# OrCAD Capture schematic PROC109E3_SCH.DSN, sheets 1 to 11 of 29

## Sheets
1 02. REVISION HISTORY: title: REVISION HISTORY; rev: E3
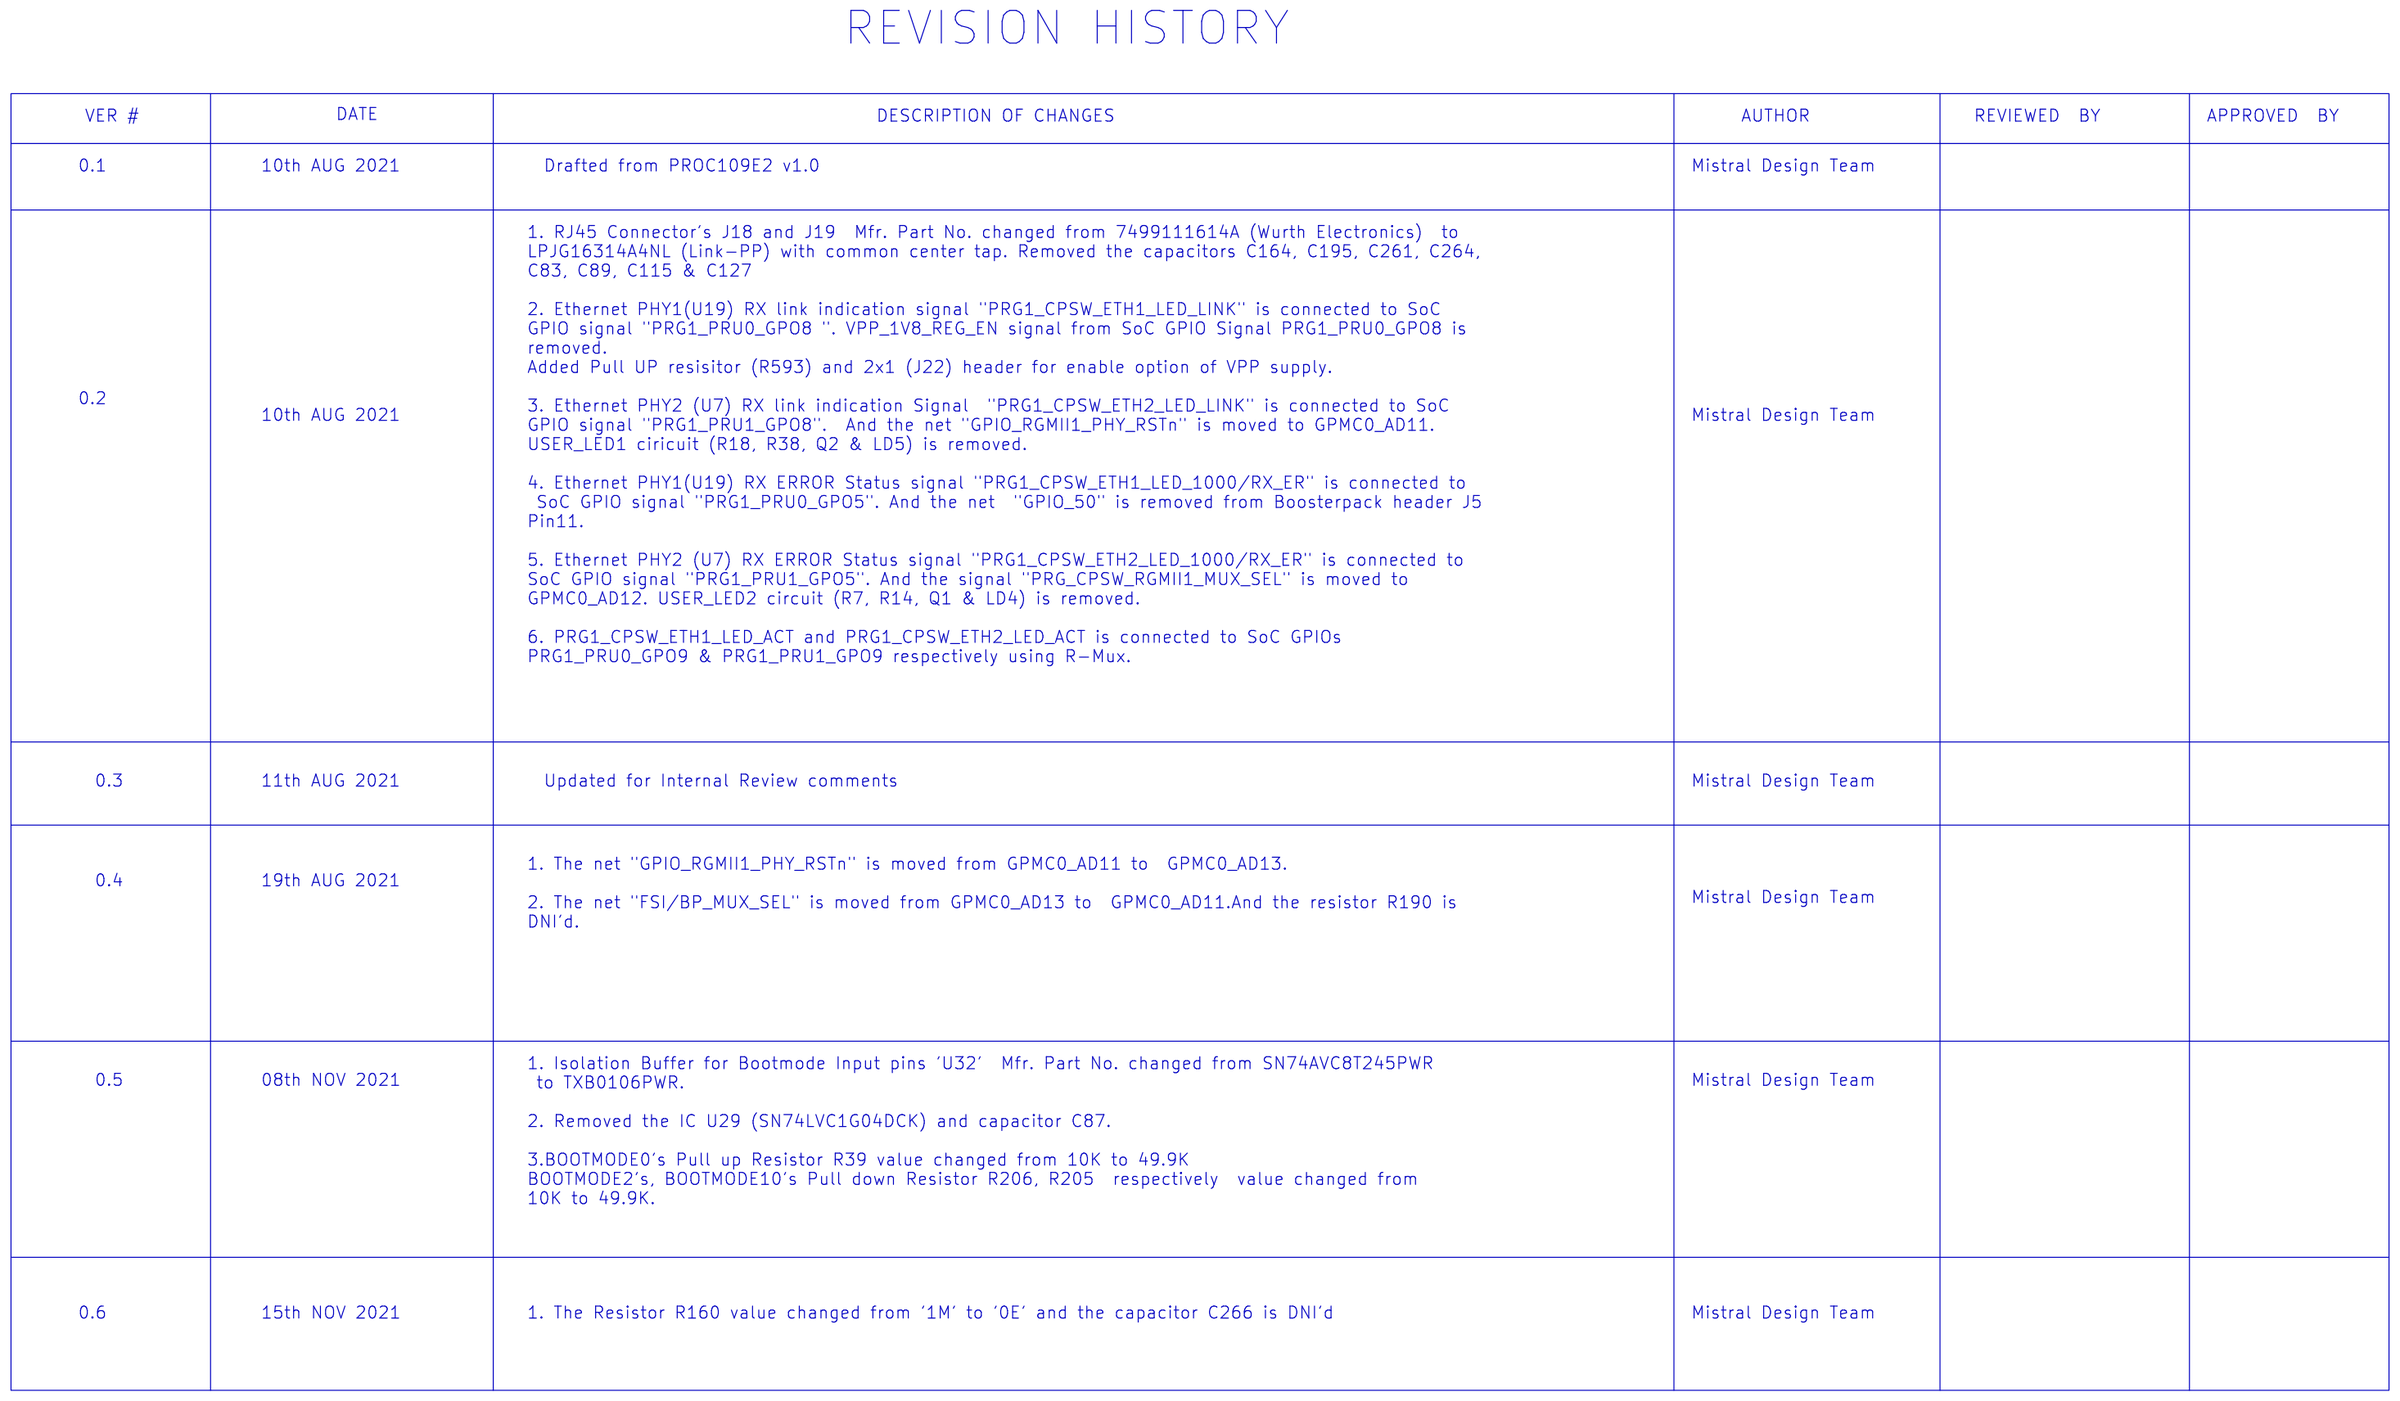
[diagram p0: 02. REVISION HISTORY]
2 01. TABLE OF CONTENTS: title: TABLE OF CONTENTS
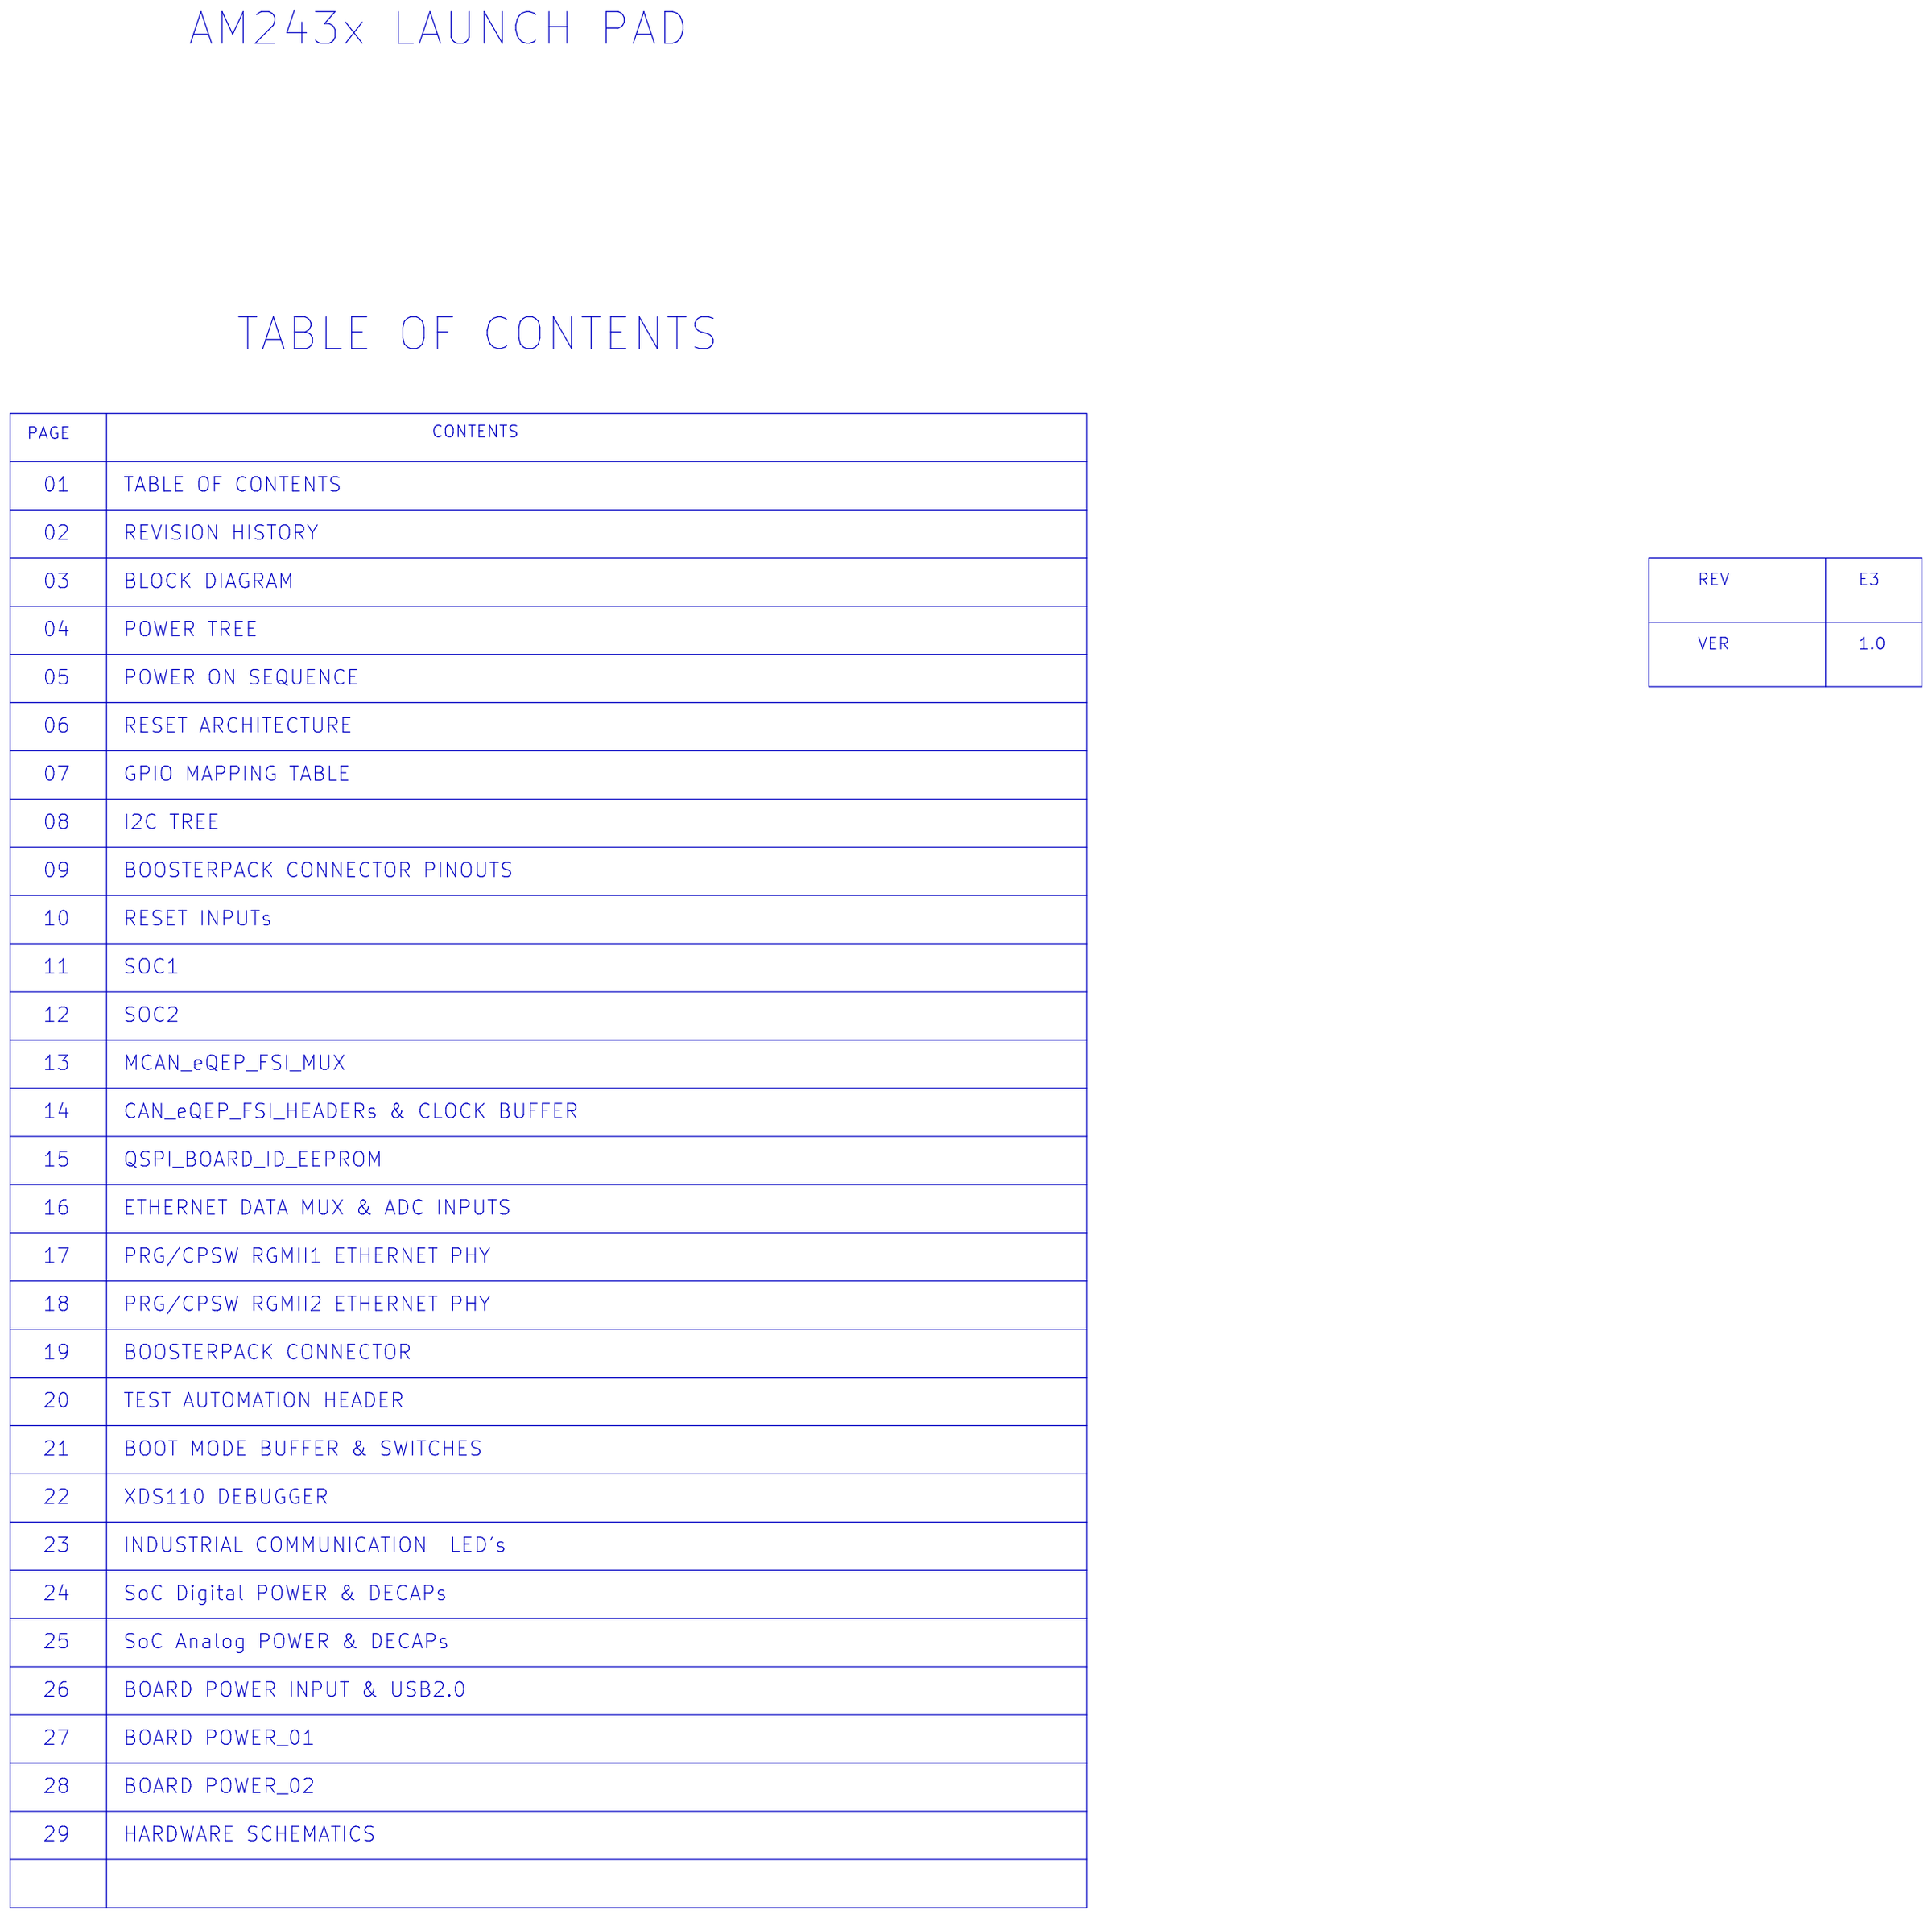
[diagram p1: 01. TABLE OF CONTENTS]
3 03. BLOCK DIAGRAM: title: BLOCK DIAGRAM
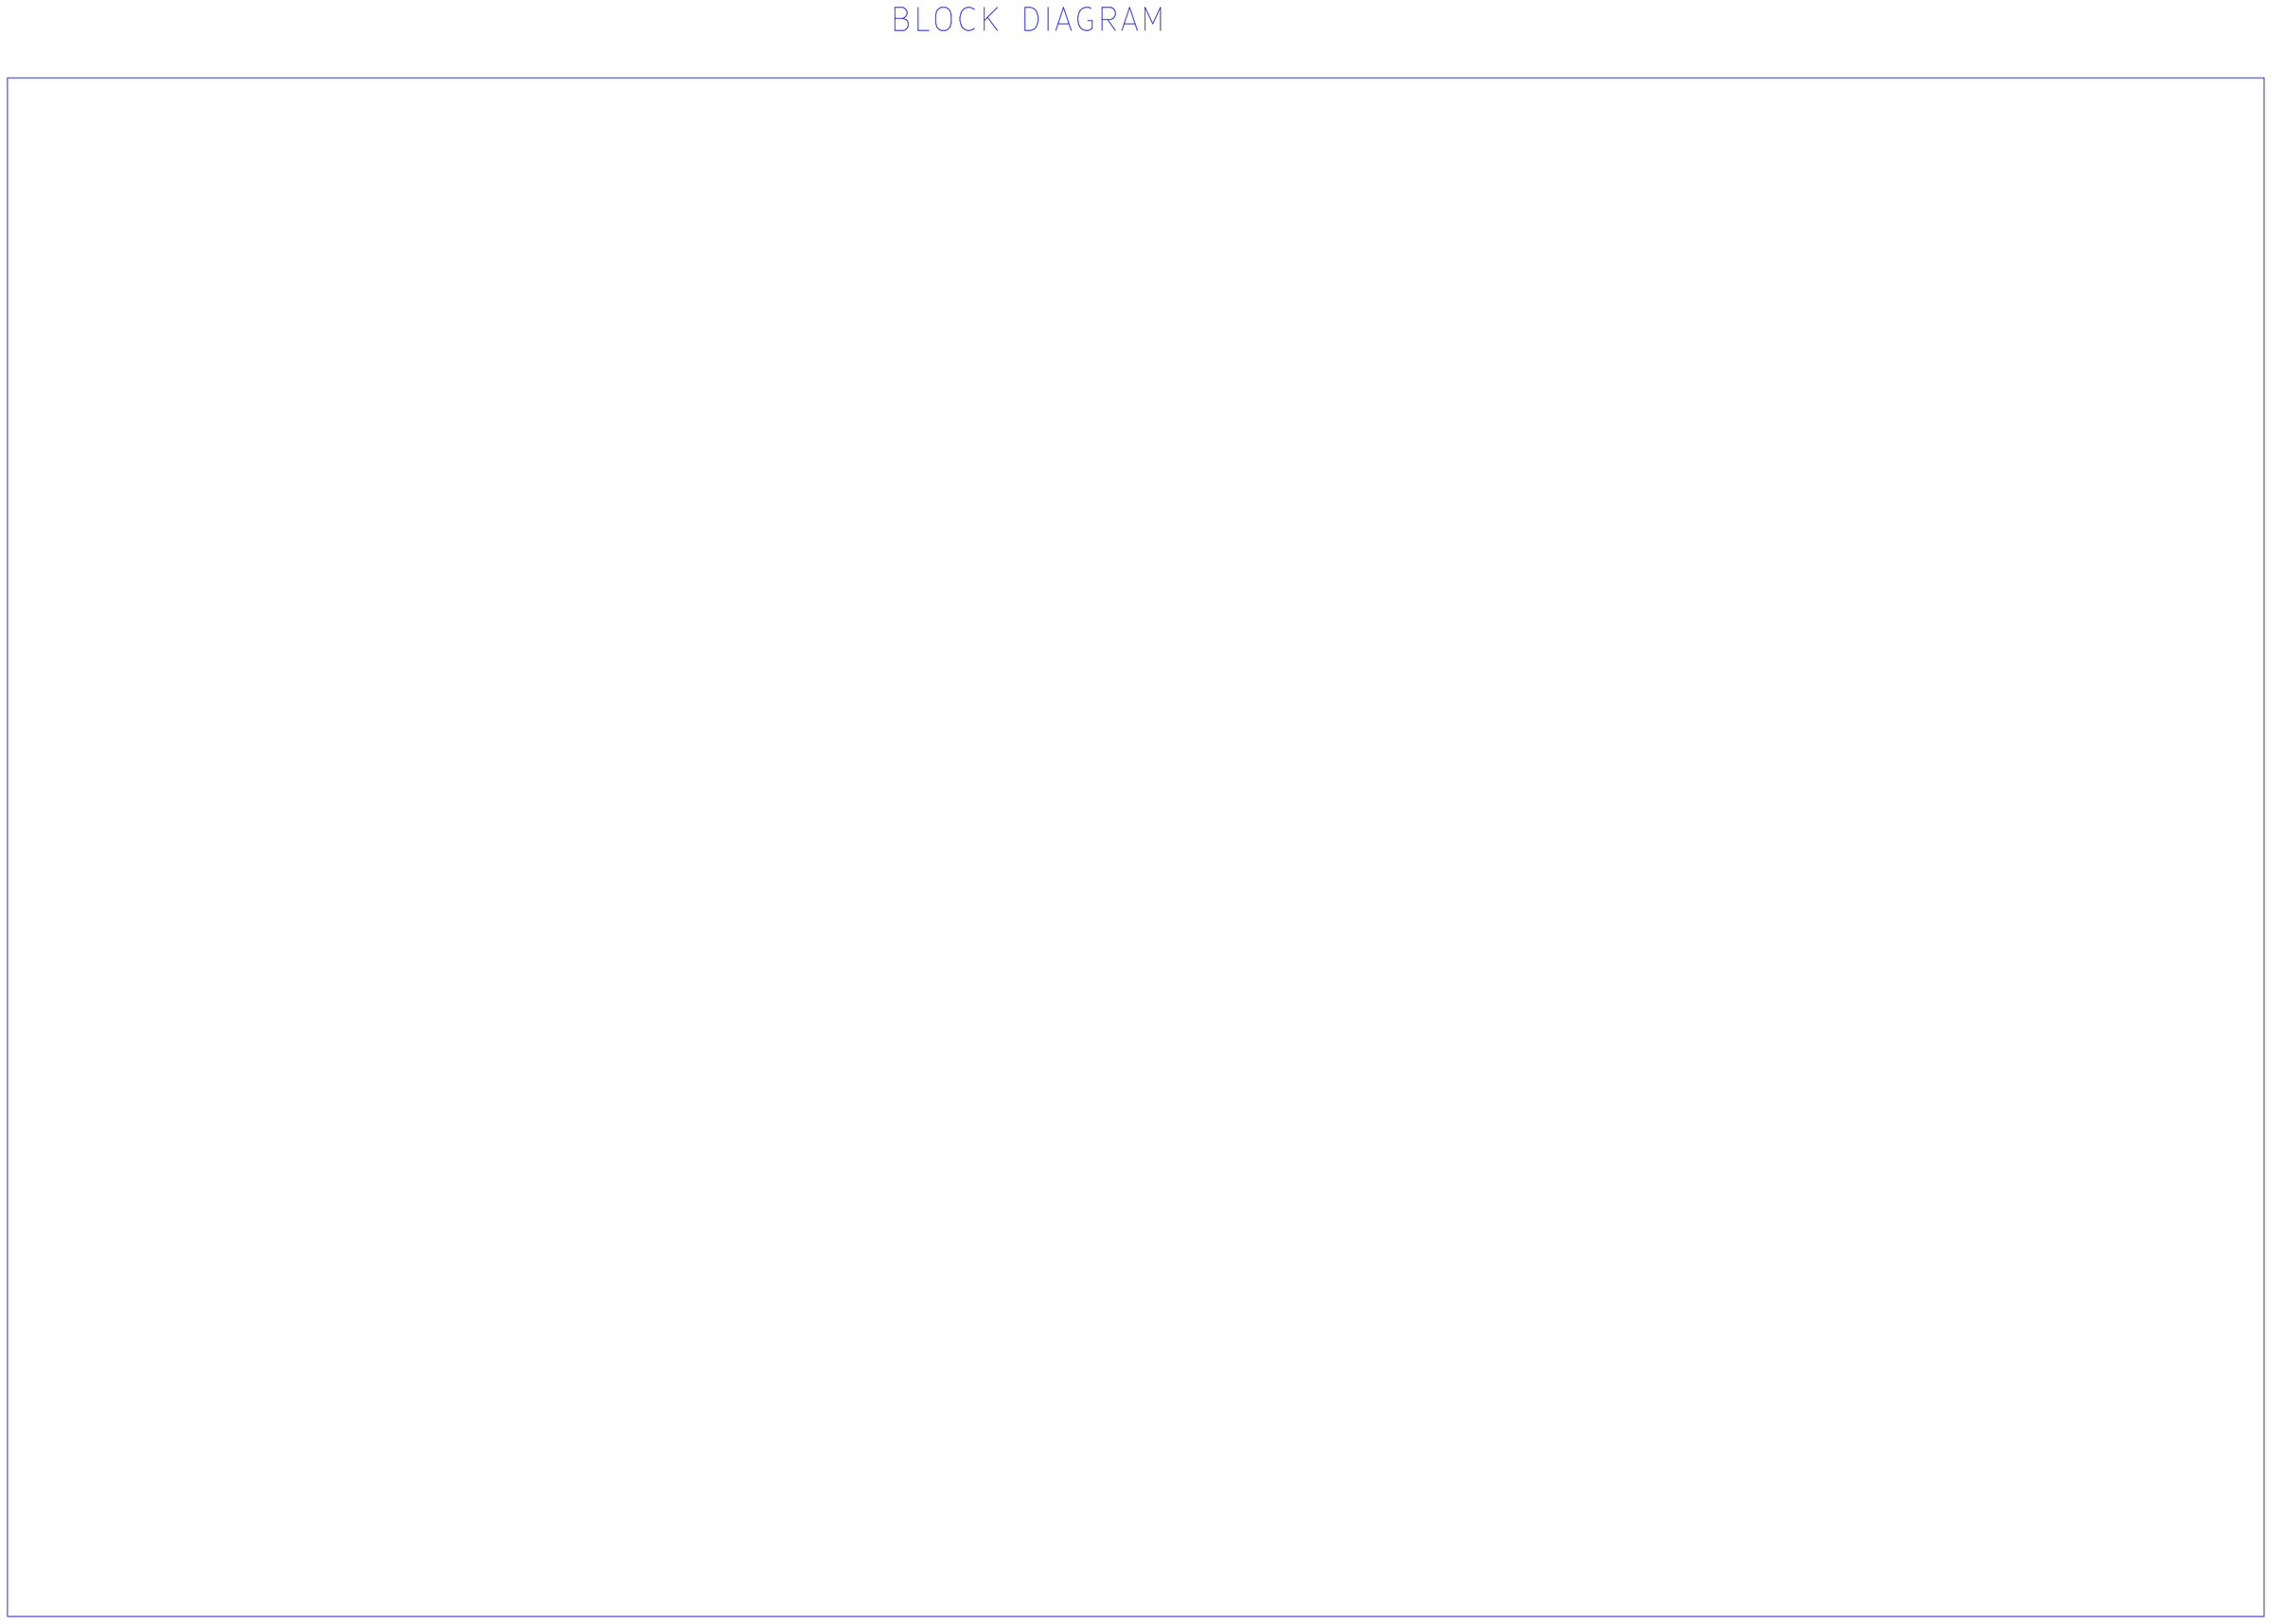
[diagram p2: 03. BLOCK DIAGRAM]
4 04. POWER TREE: title: POWER TREE
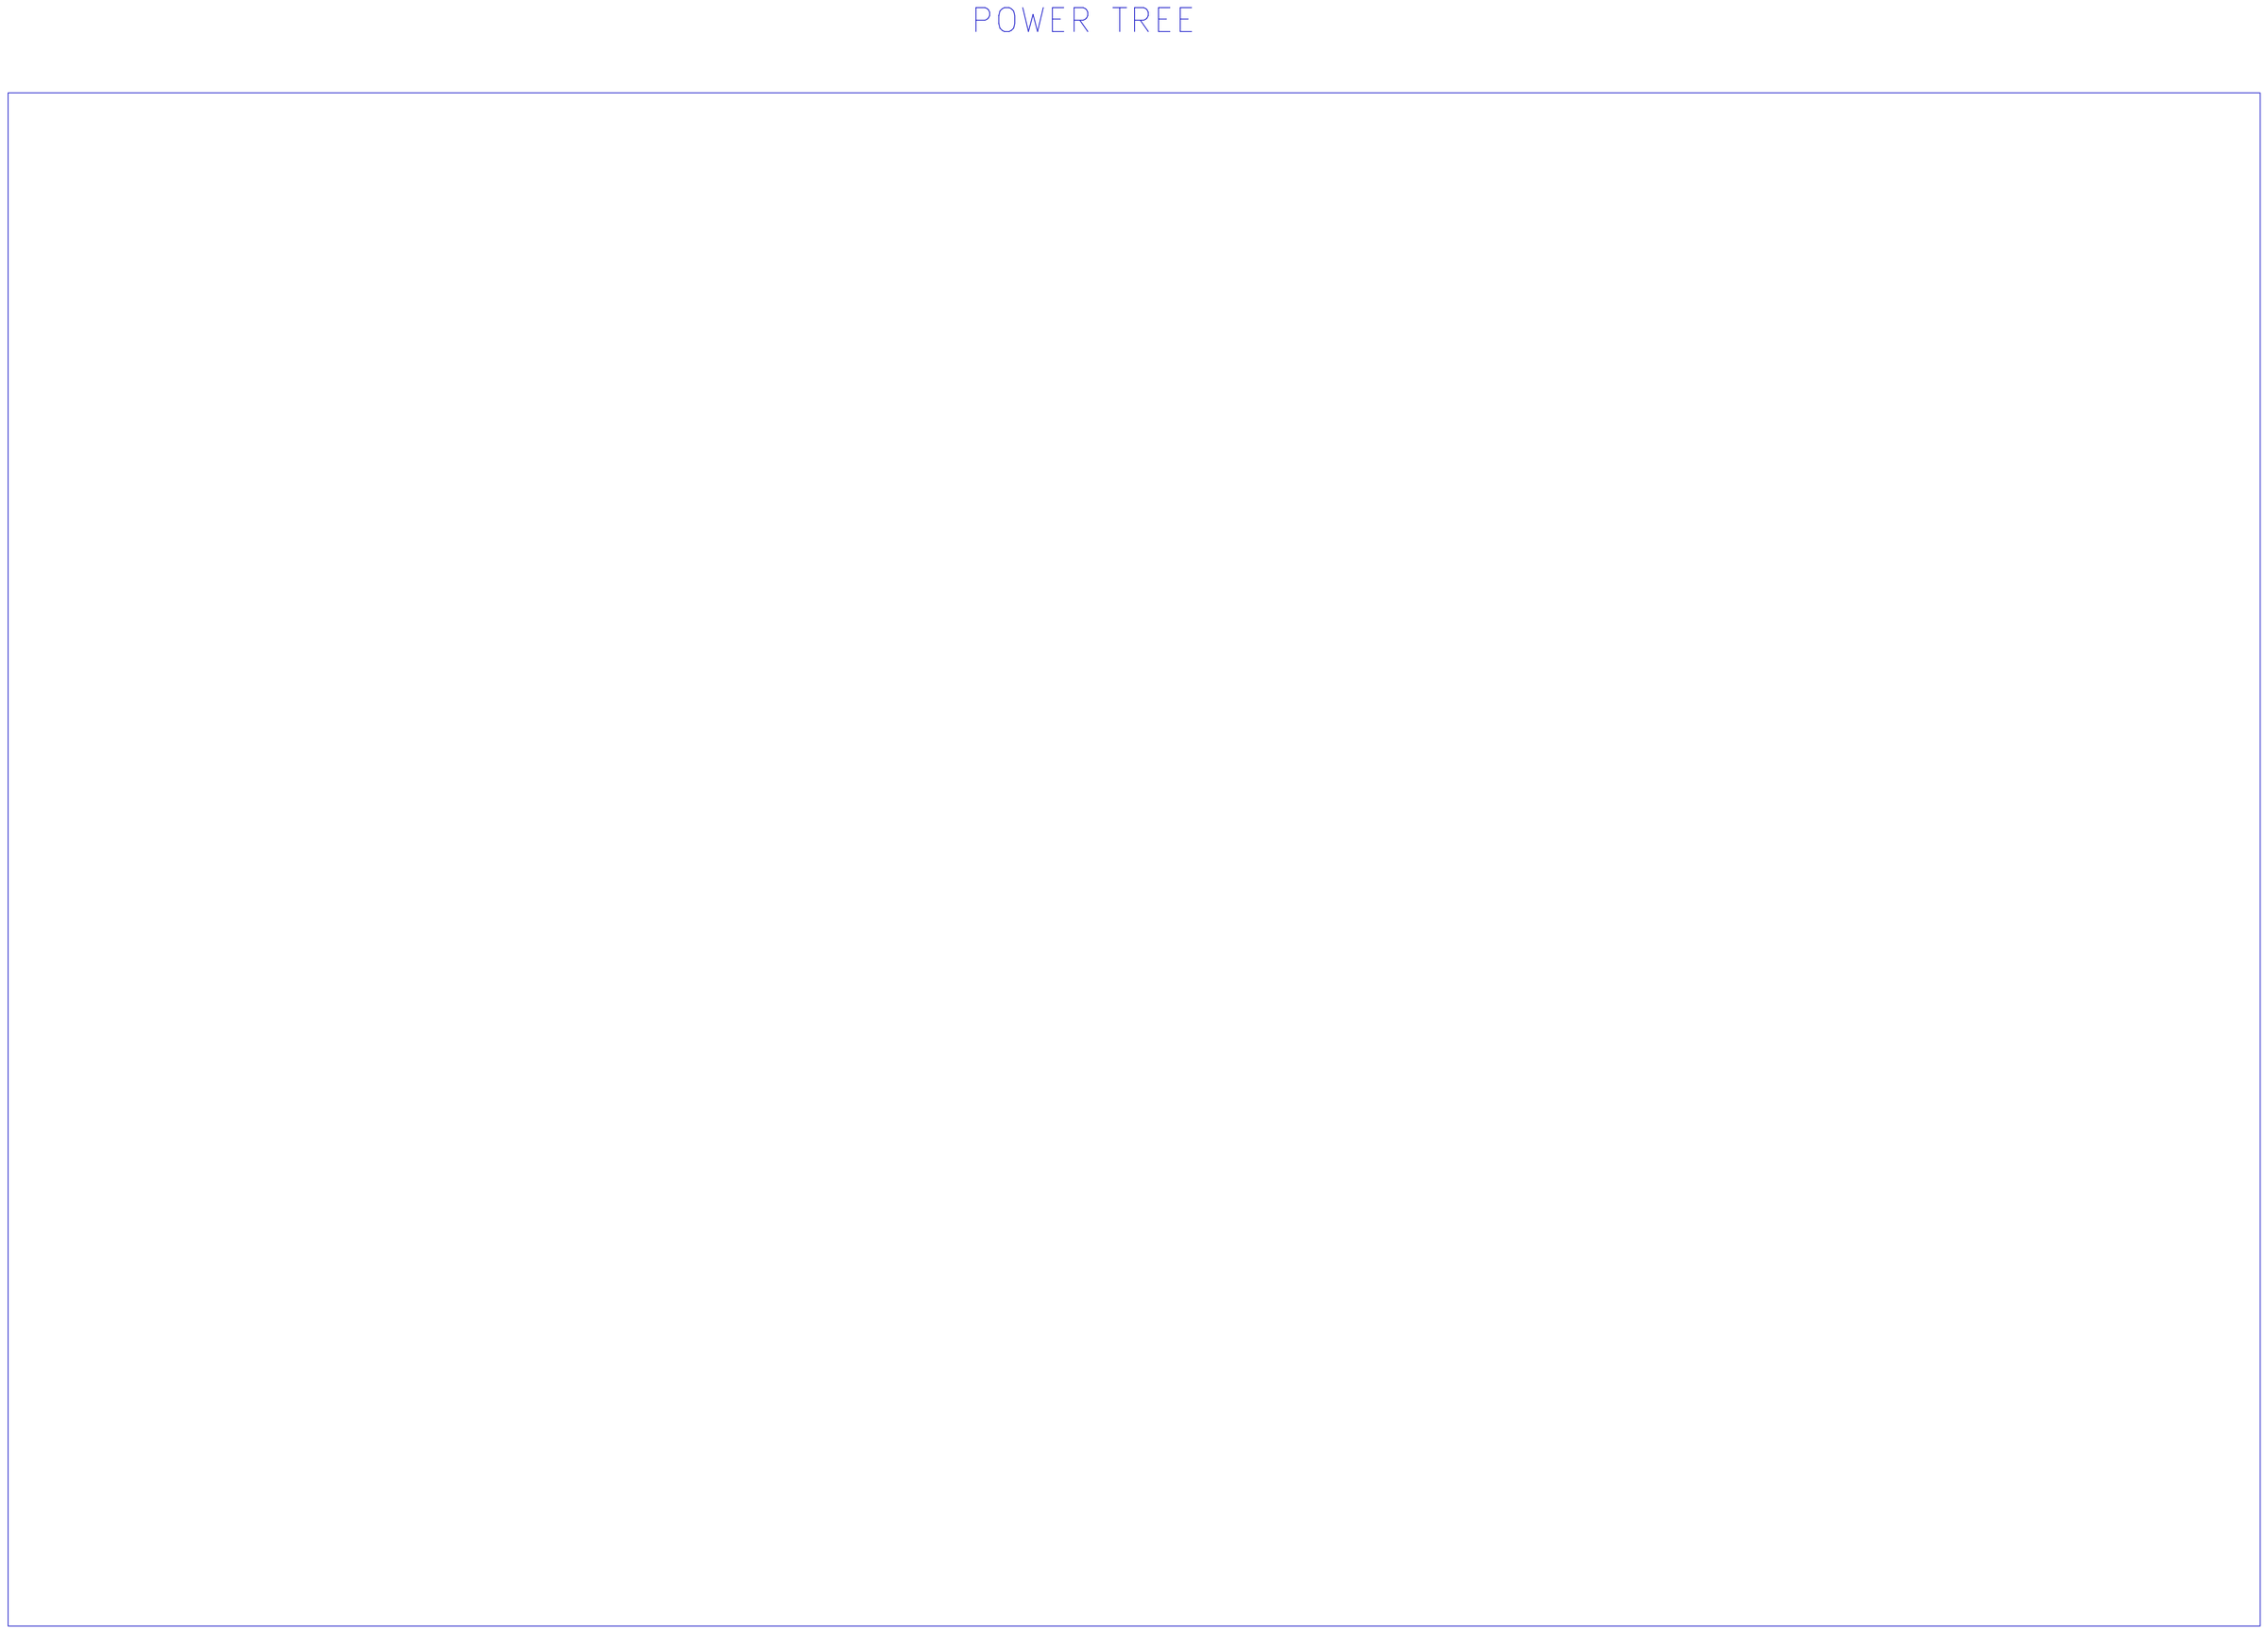
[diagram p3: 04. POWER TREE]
5 05. POWER ON SEQUENCE: title: POWER ON SEQUENCE
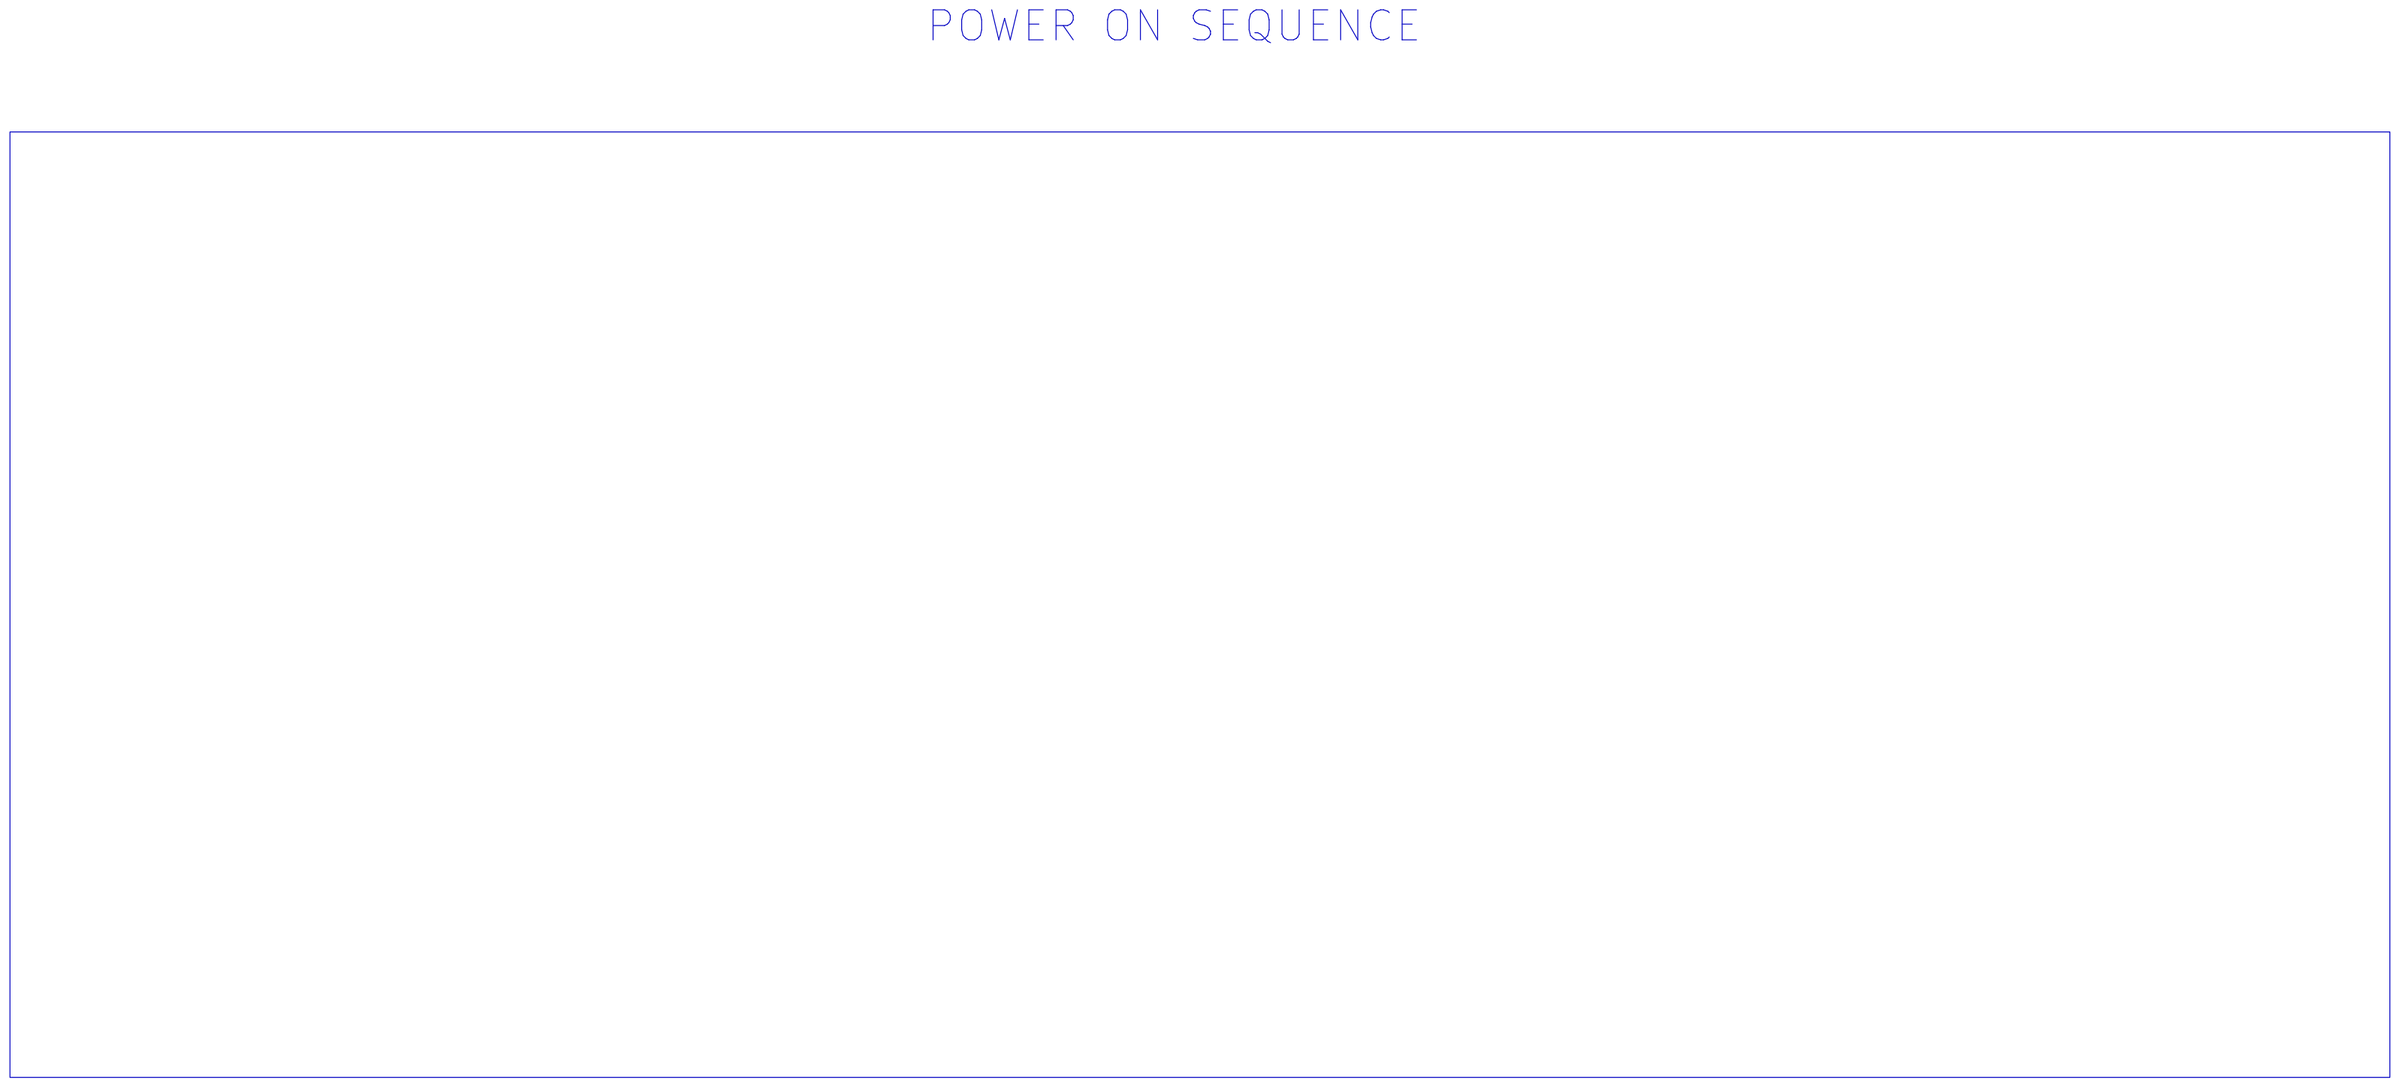
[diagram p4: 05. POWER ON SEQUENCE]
6 06. RESET ARCHITECTURE: title: RESET ARCHITECTURE
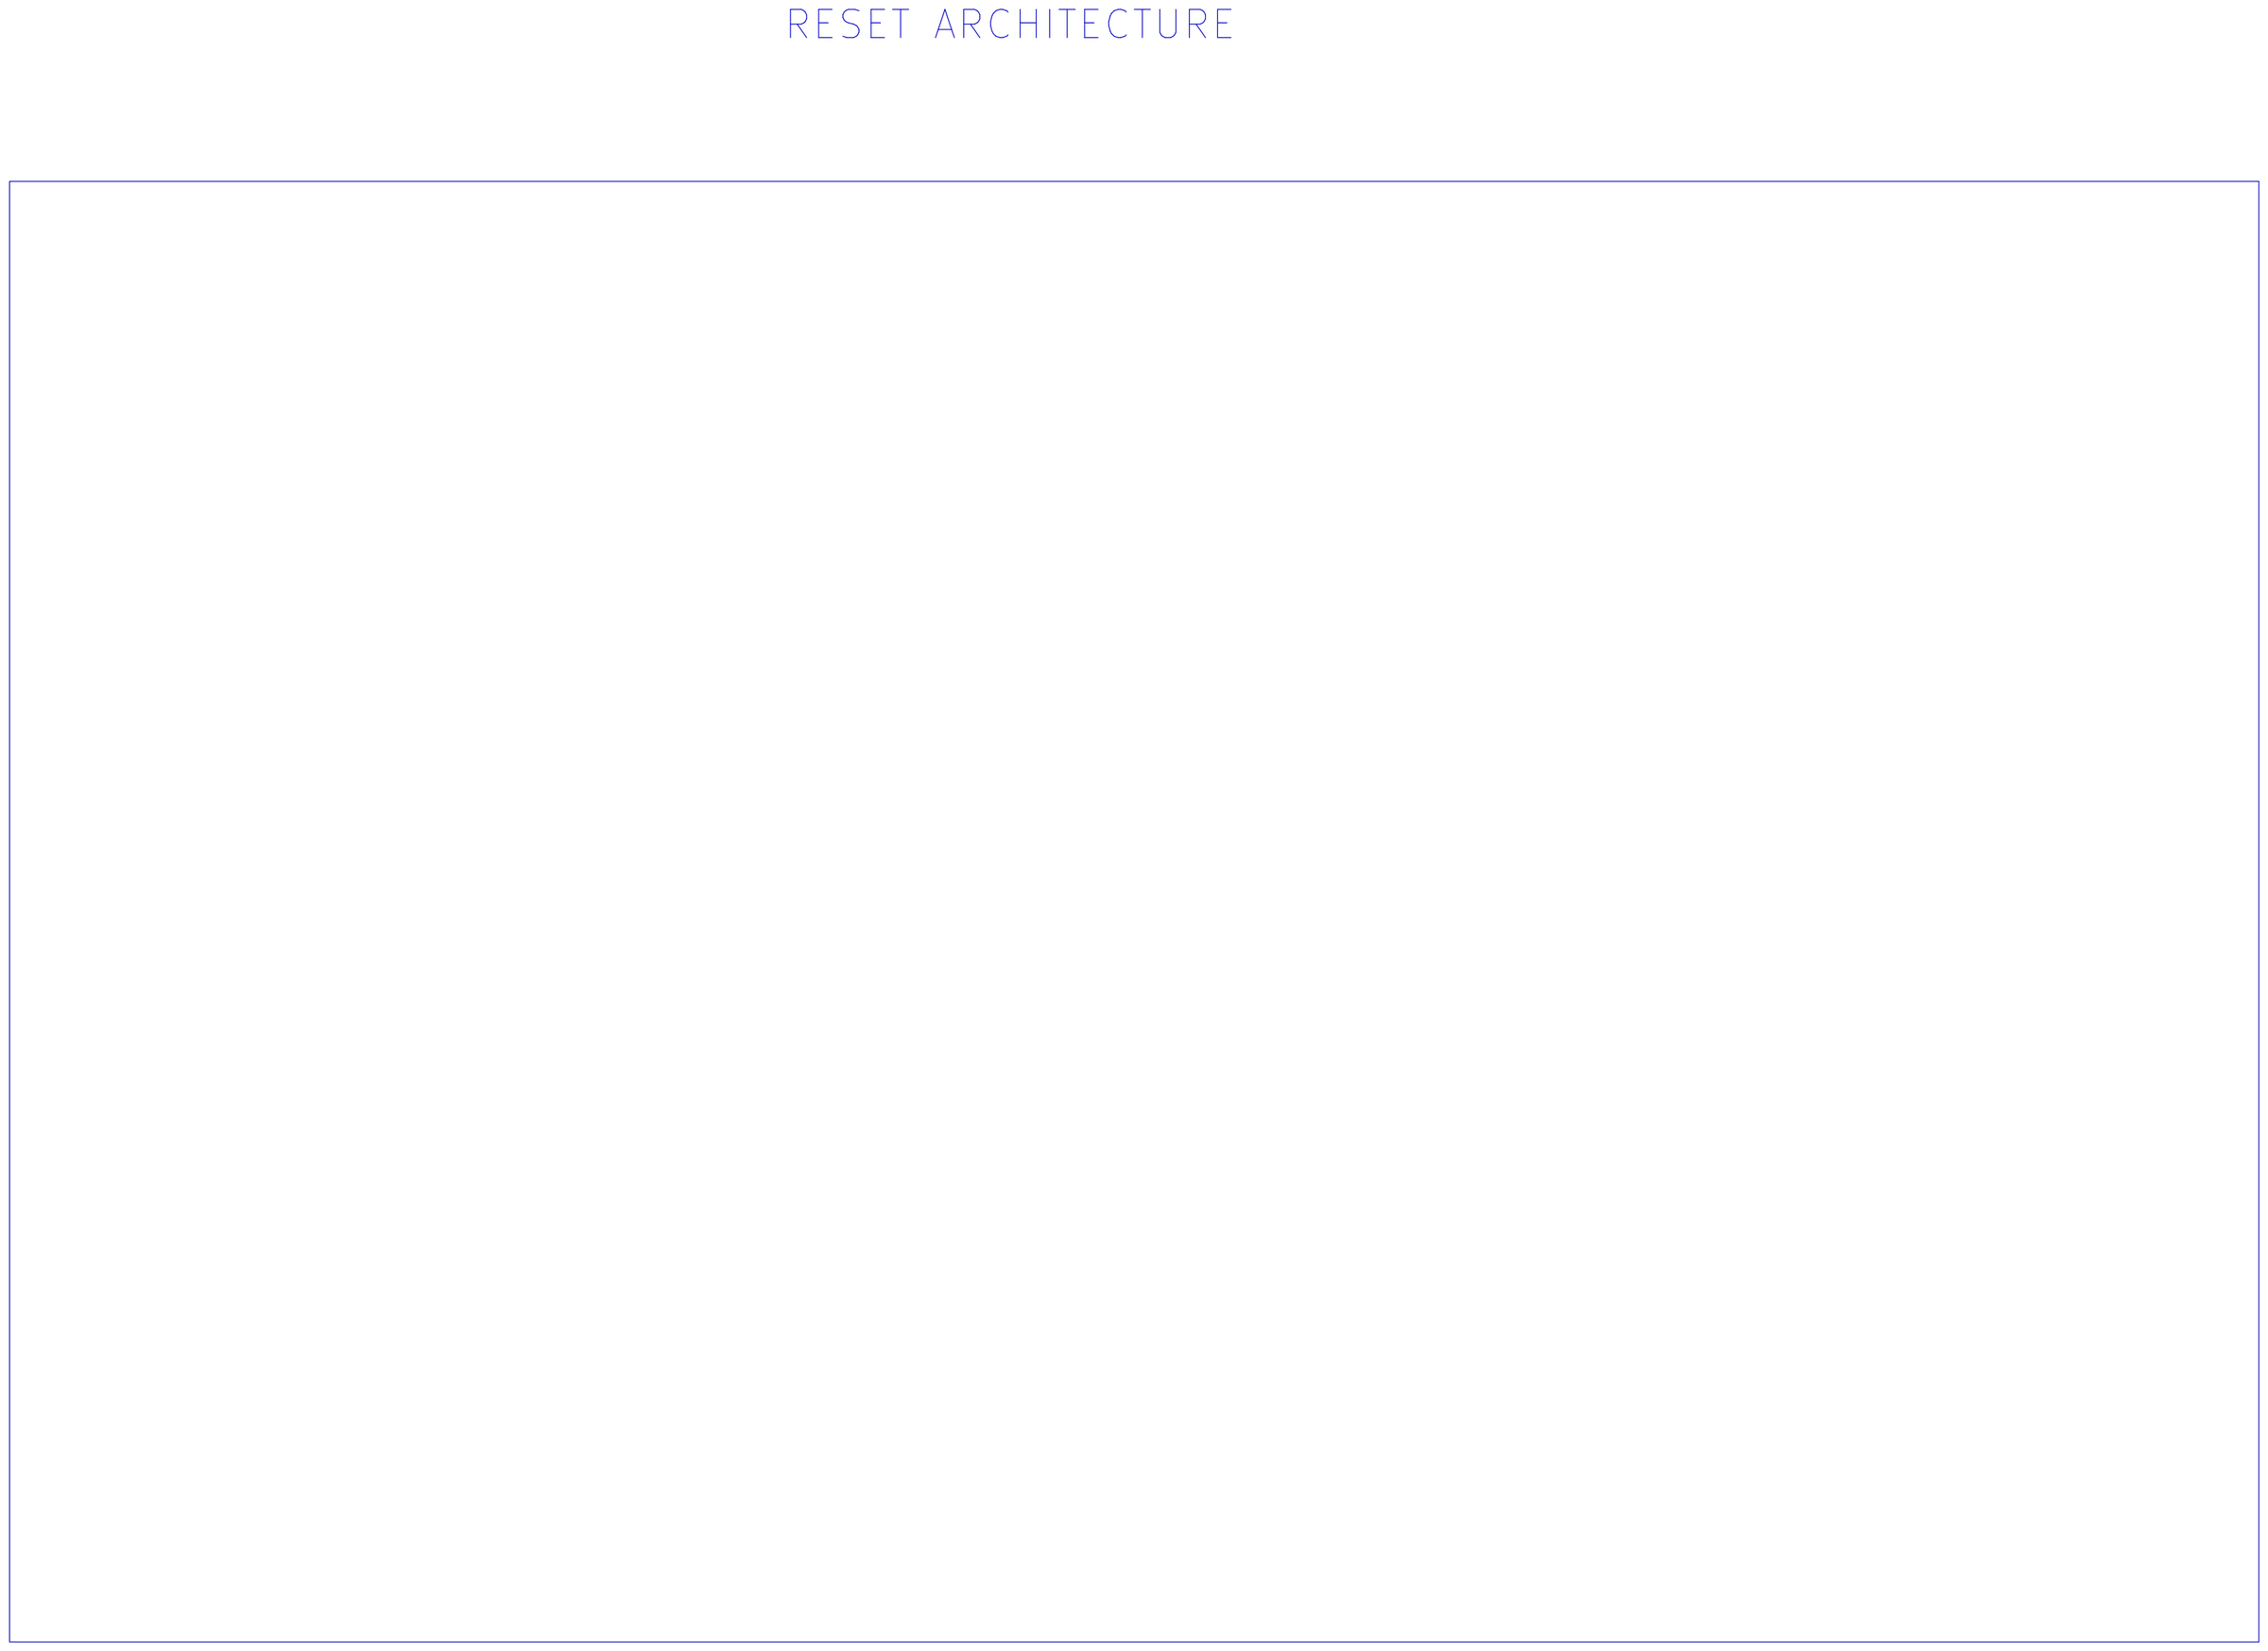
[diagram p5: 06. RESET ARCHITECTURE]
7 07. GPIO MAPPING TABLE: title: GPIO MAPPING TABLE
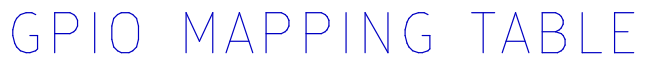
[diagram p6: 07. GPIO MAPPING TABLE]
8 08. I2C TREE: title: I2C TREE
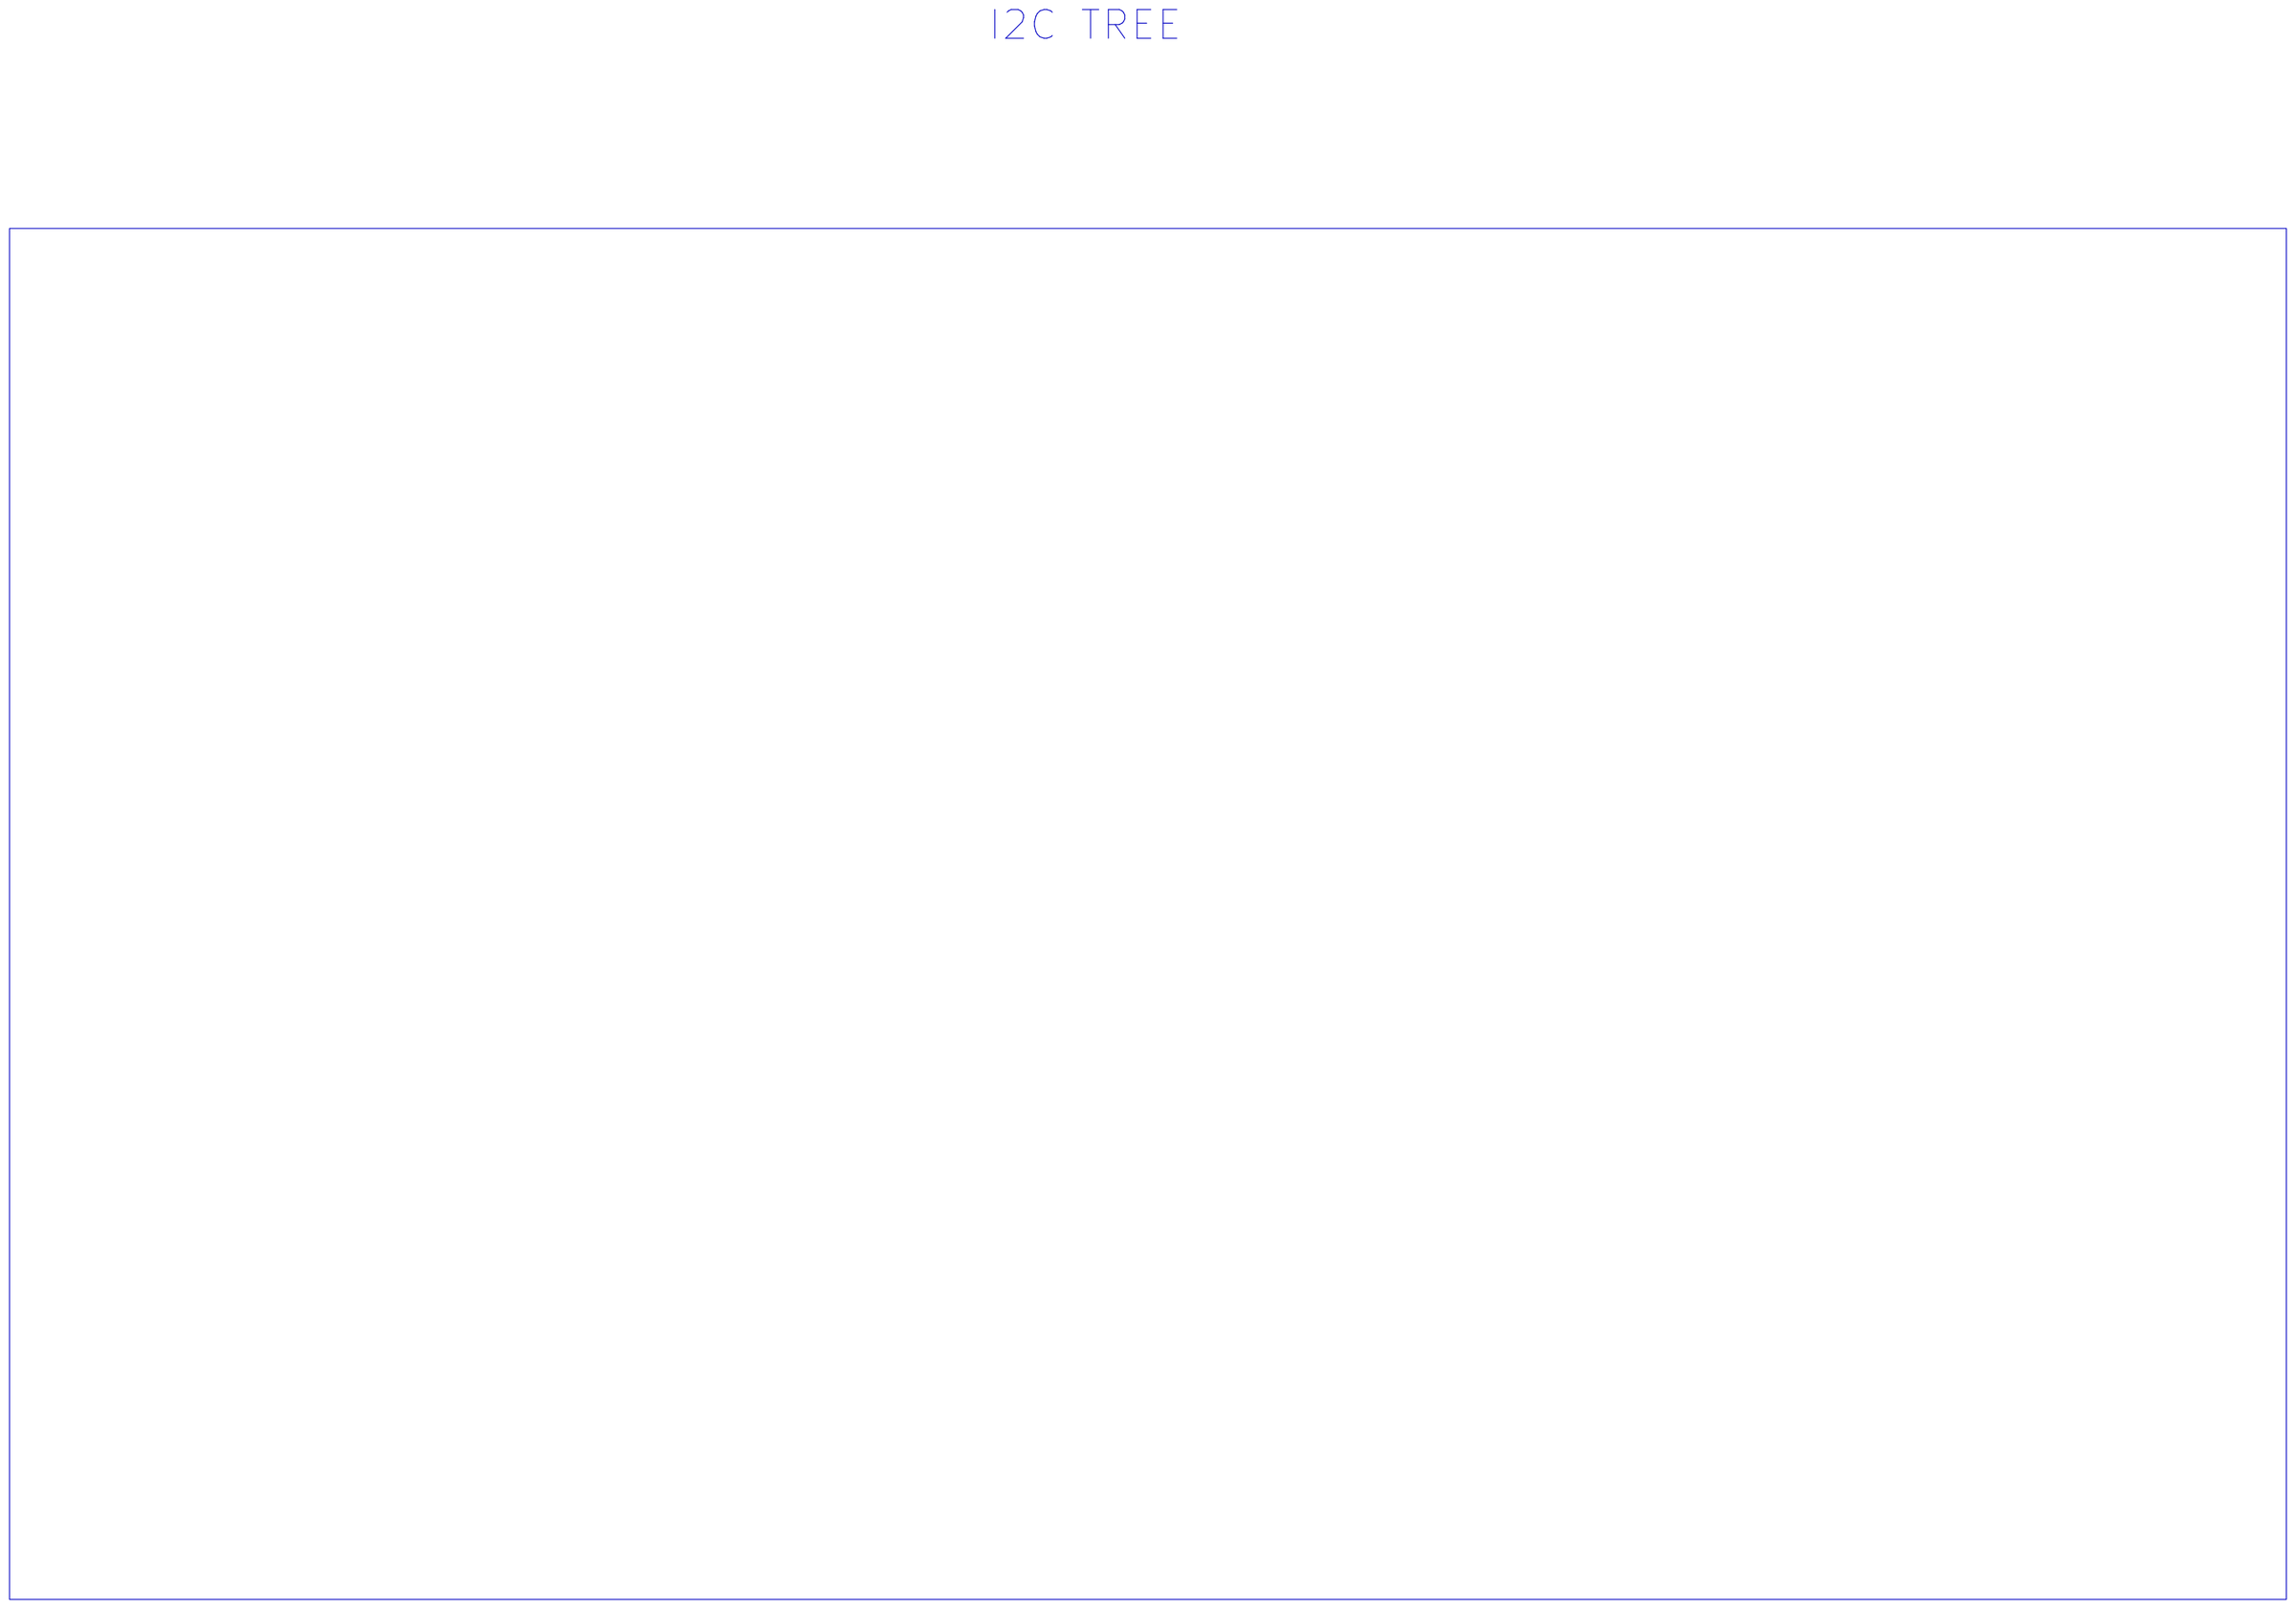
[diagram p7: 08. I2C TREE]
9 09. BOOSTERPACK CONN PINOUTs: title: BOOSTERPACK CONNECTOR PINOUTS
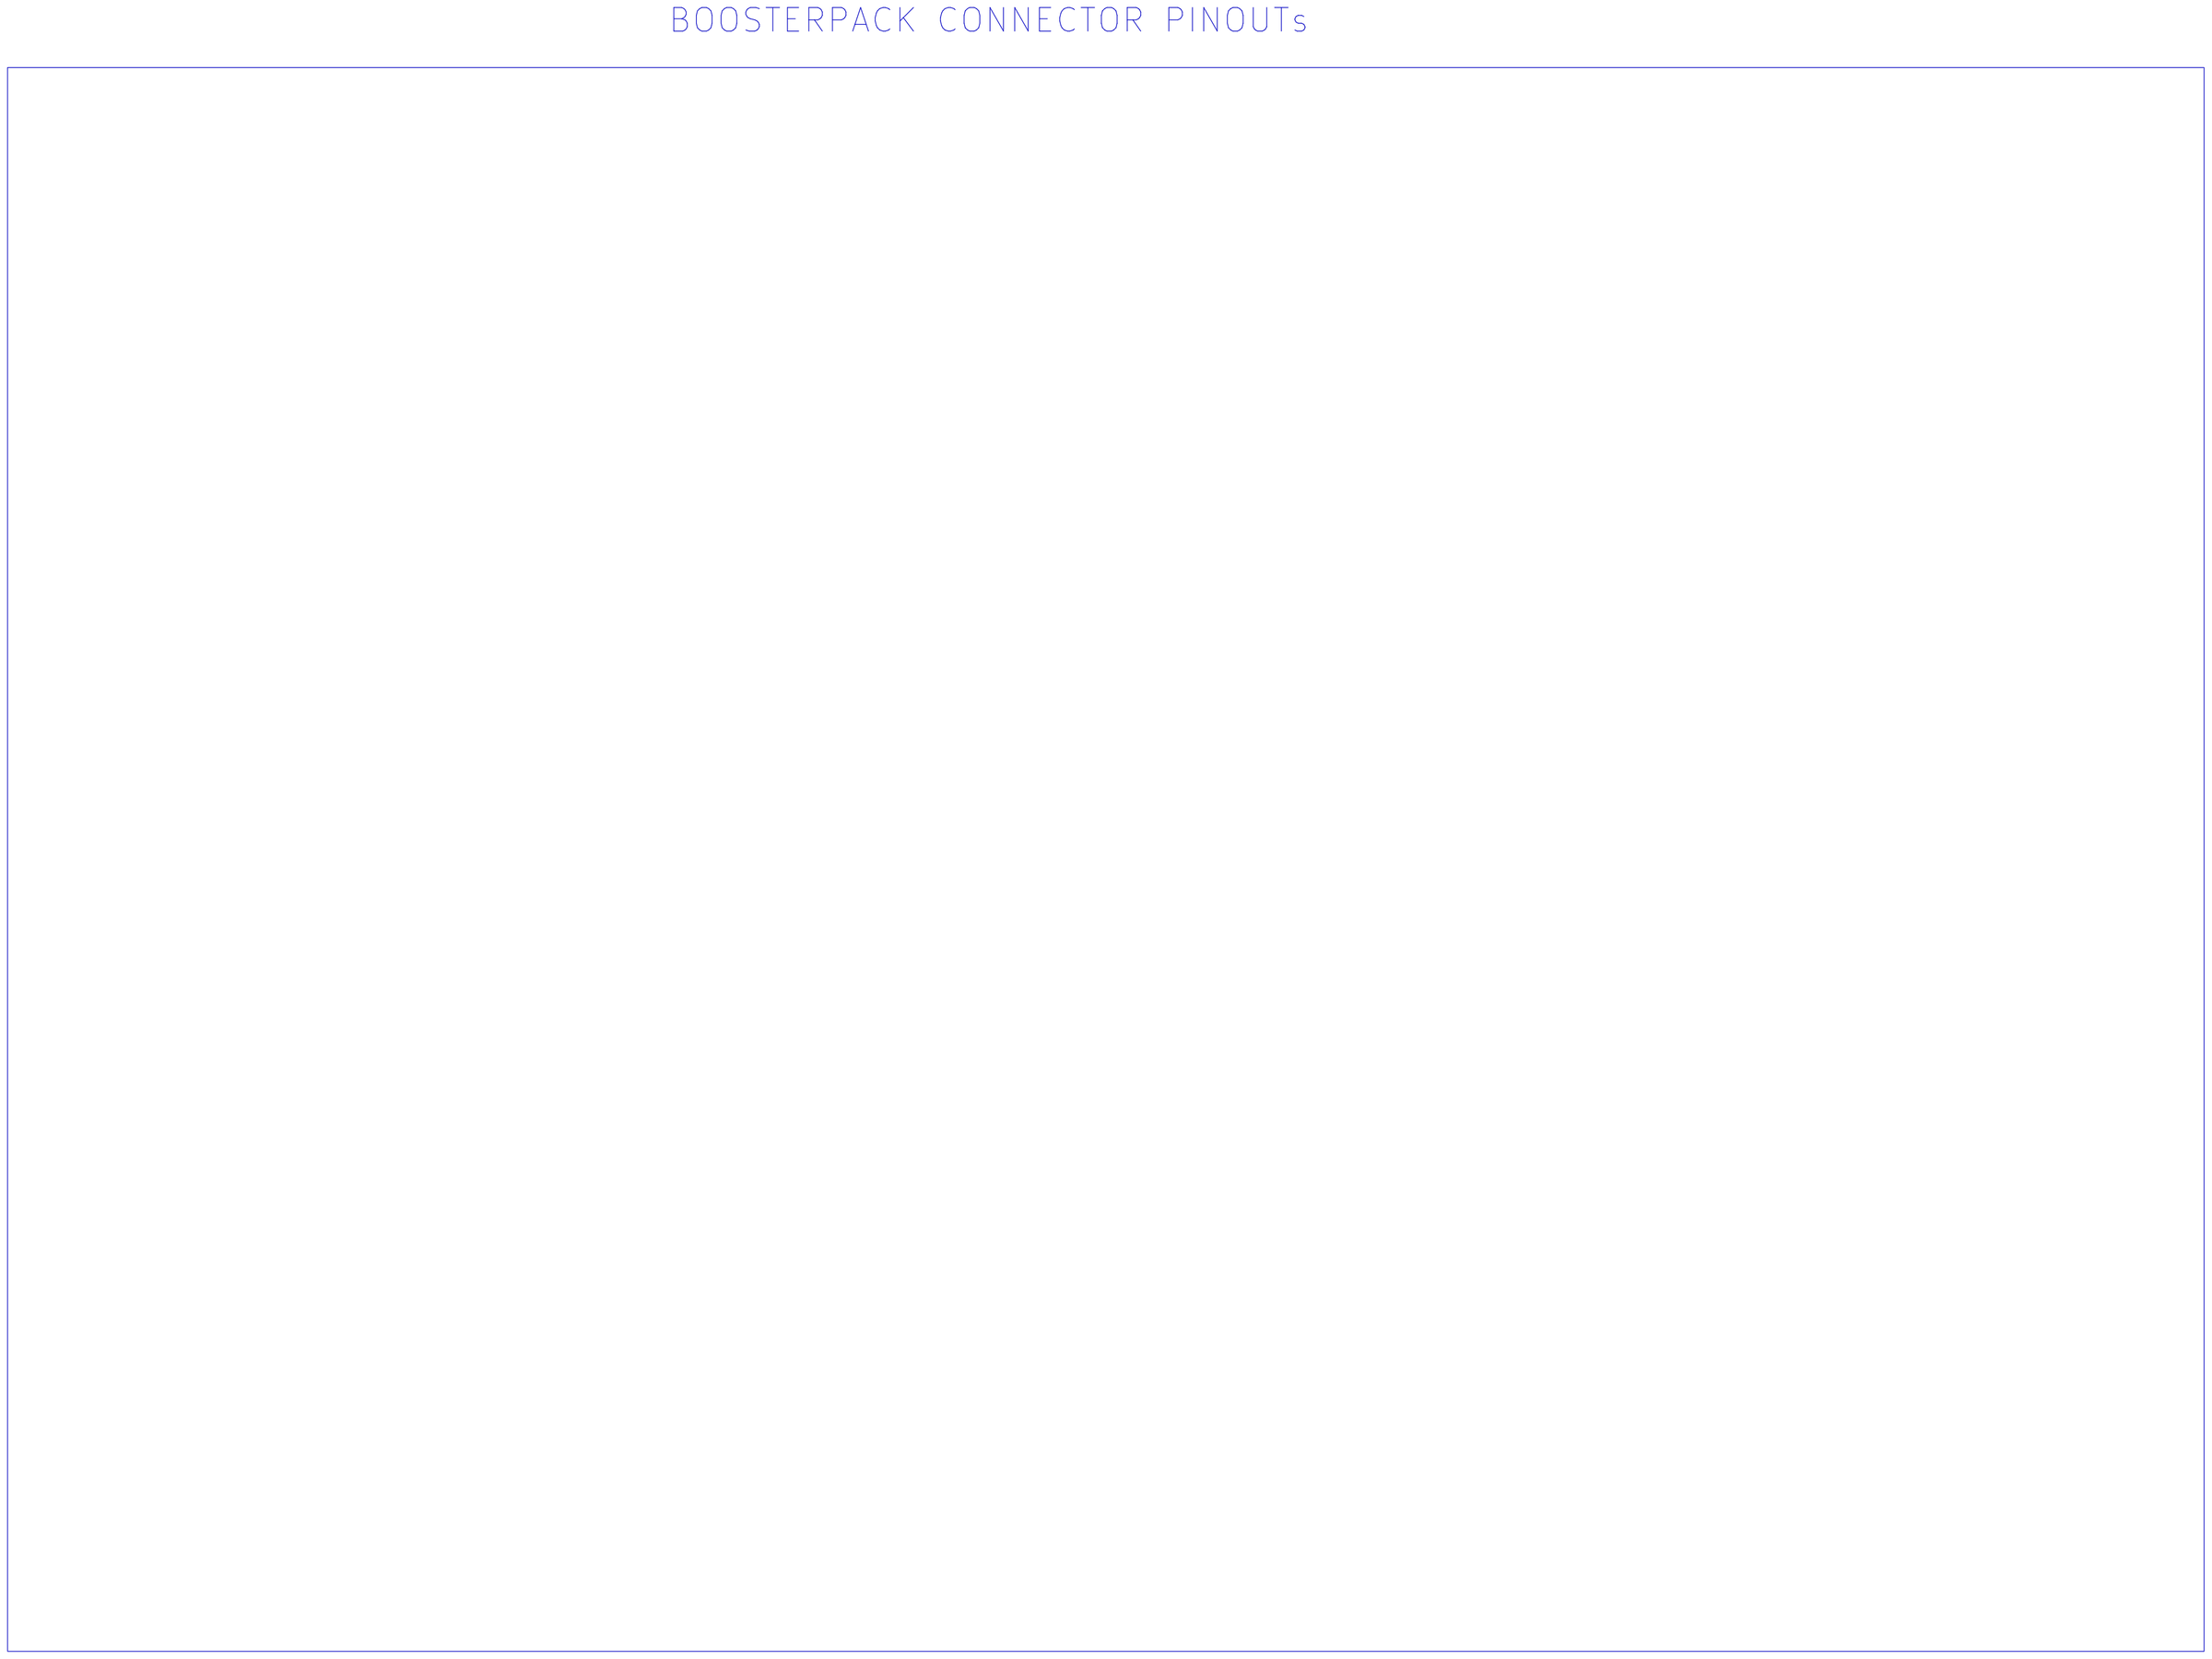
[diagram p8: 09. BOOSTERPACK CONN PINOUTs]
10 10. RESET_INPUTs: size C; title: RESET INPUTs
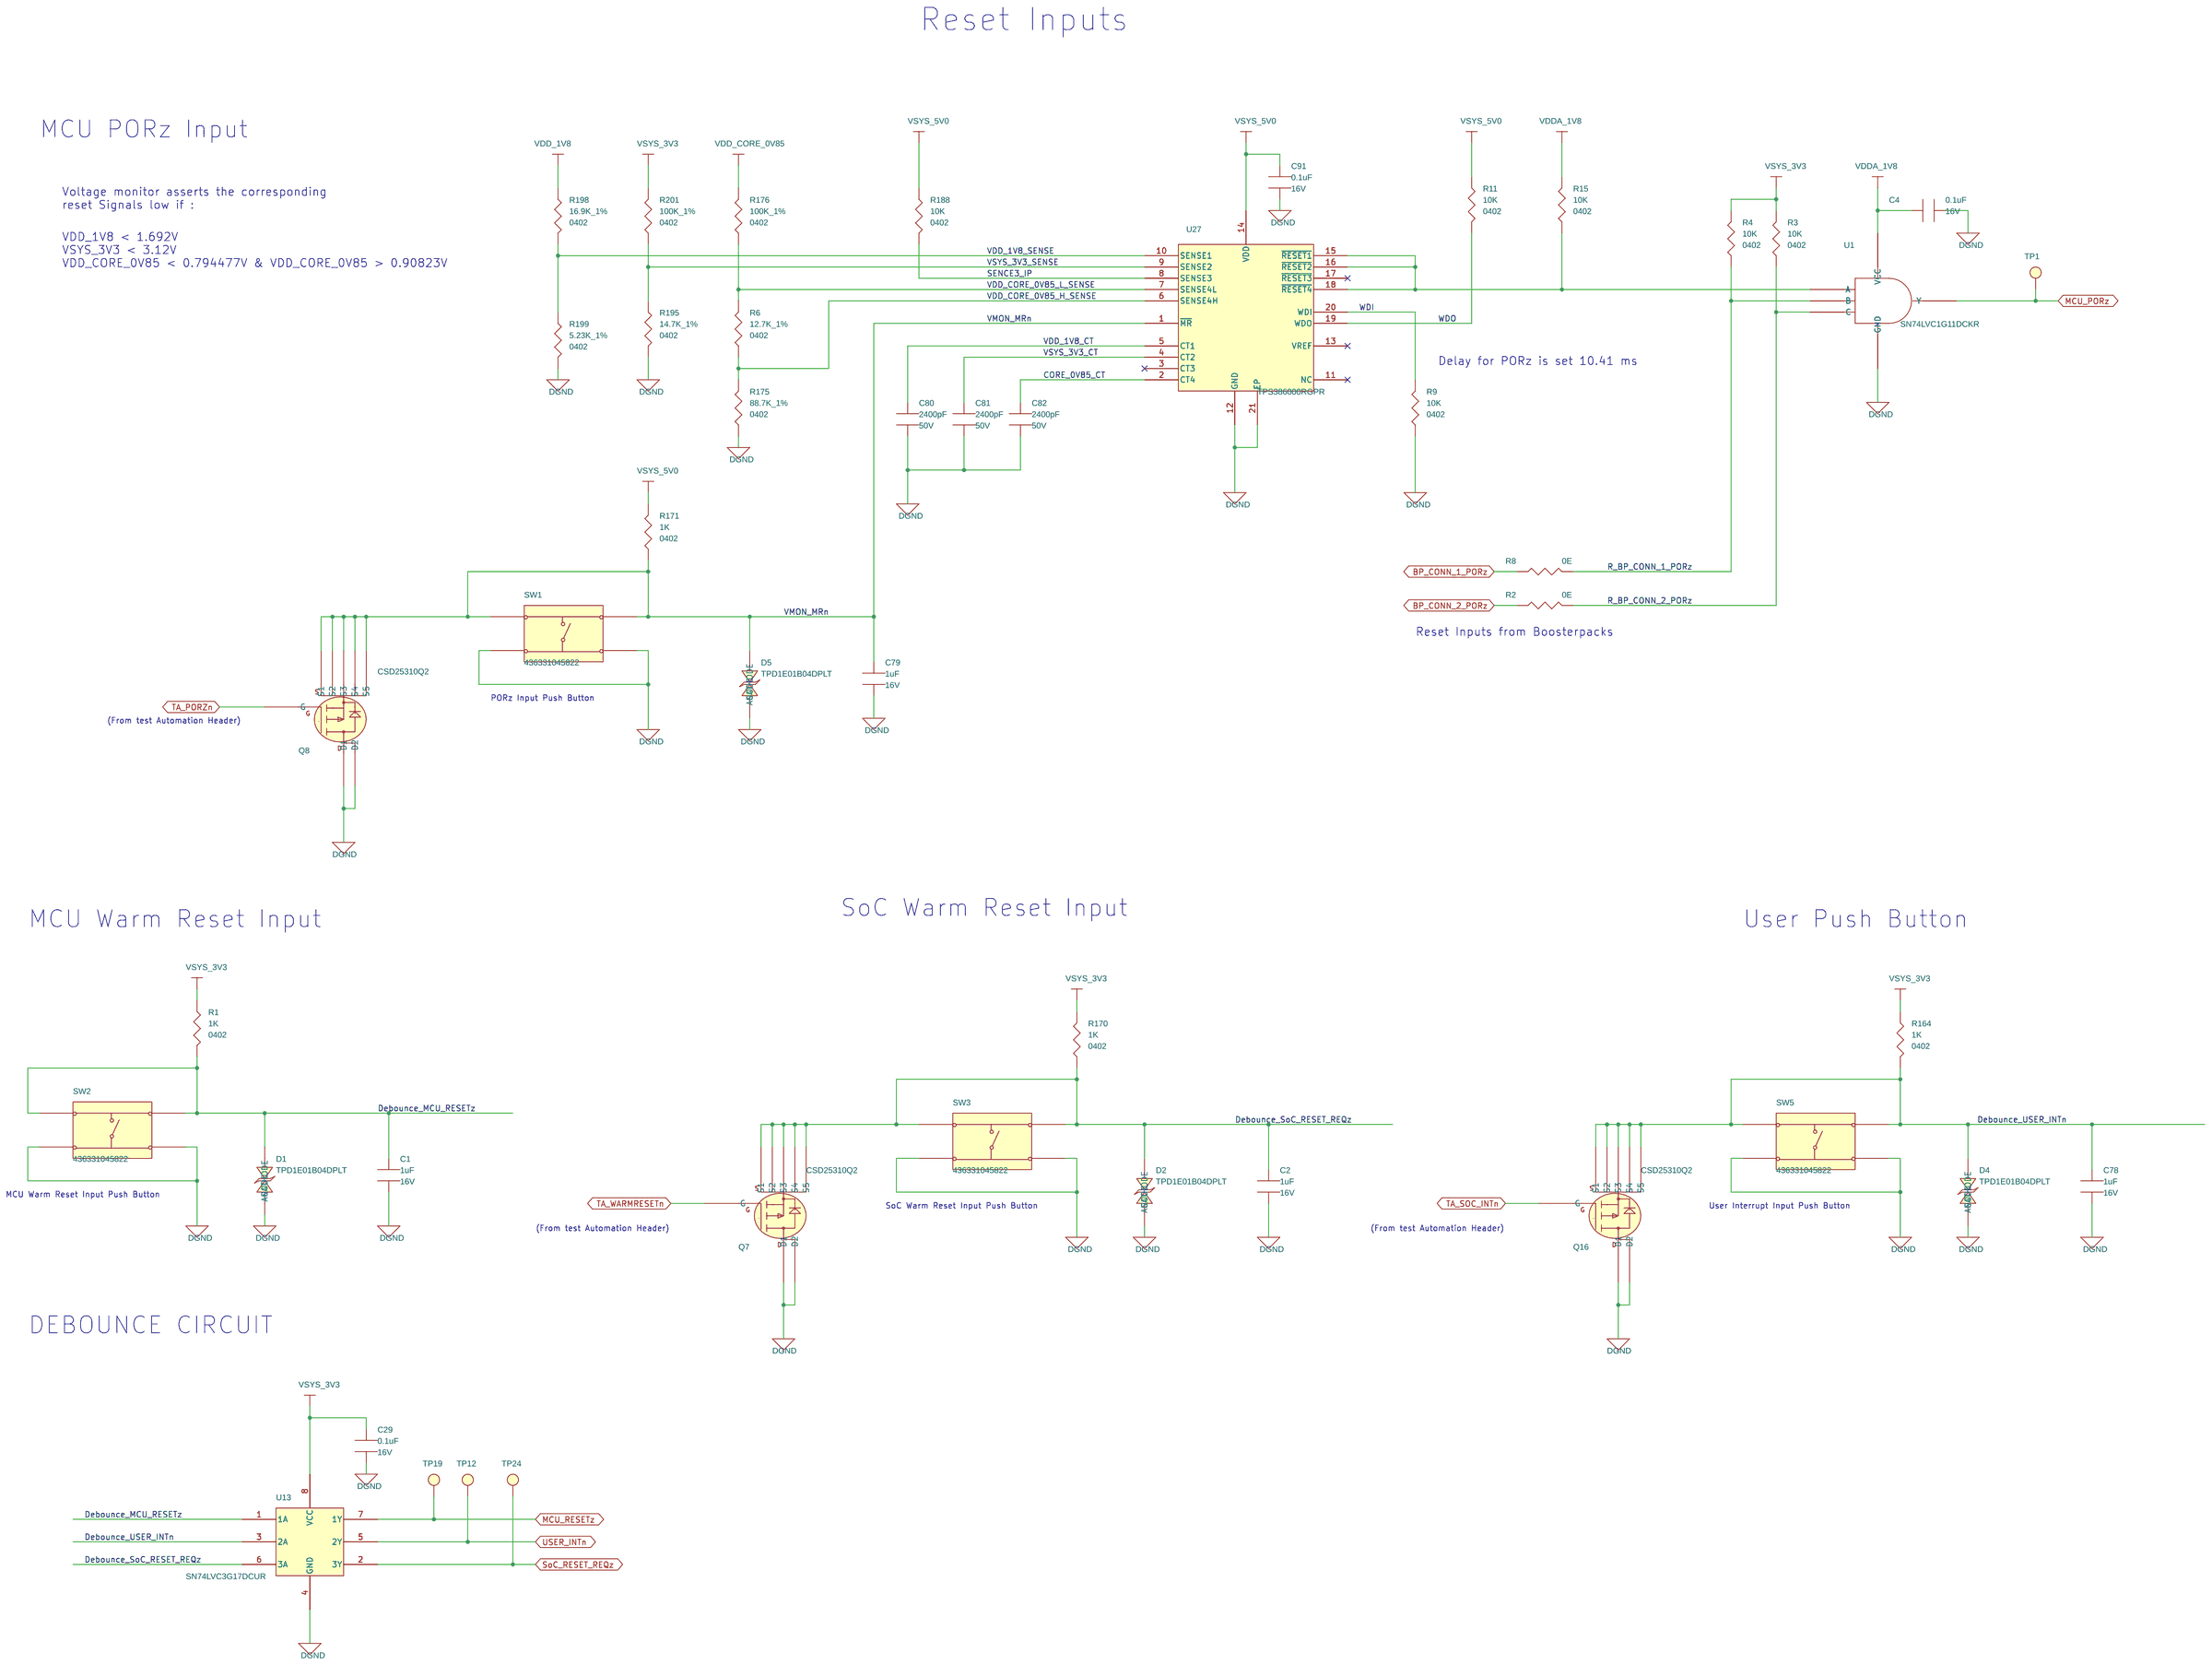
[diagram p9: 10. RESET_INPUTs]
11 11. SOC1: size C; title: SOC1
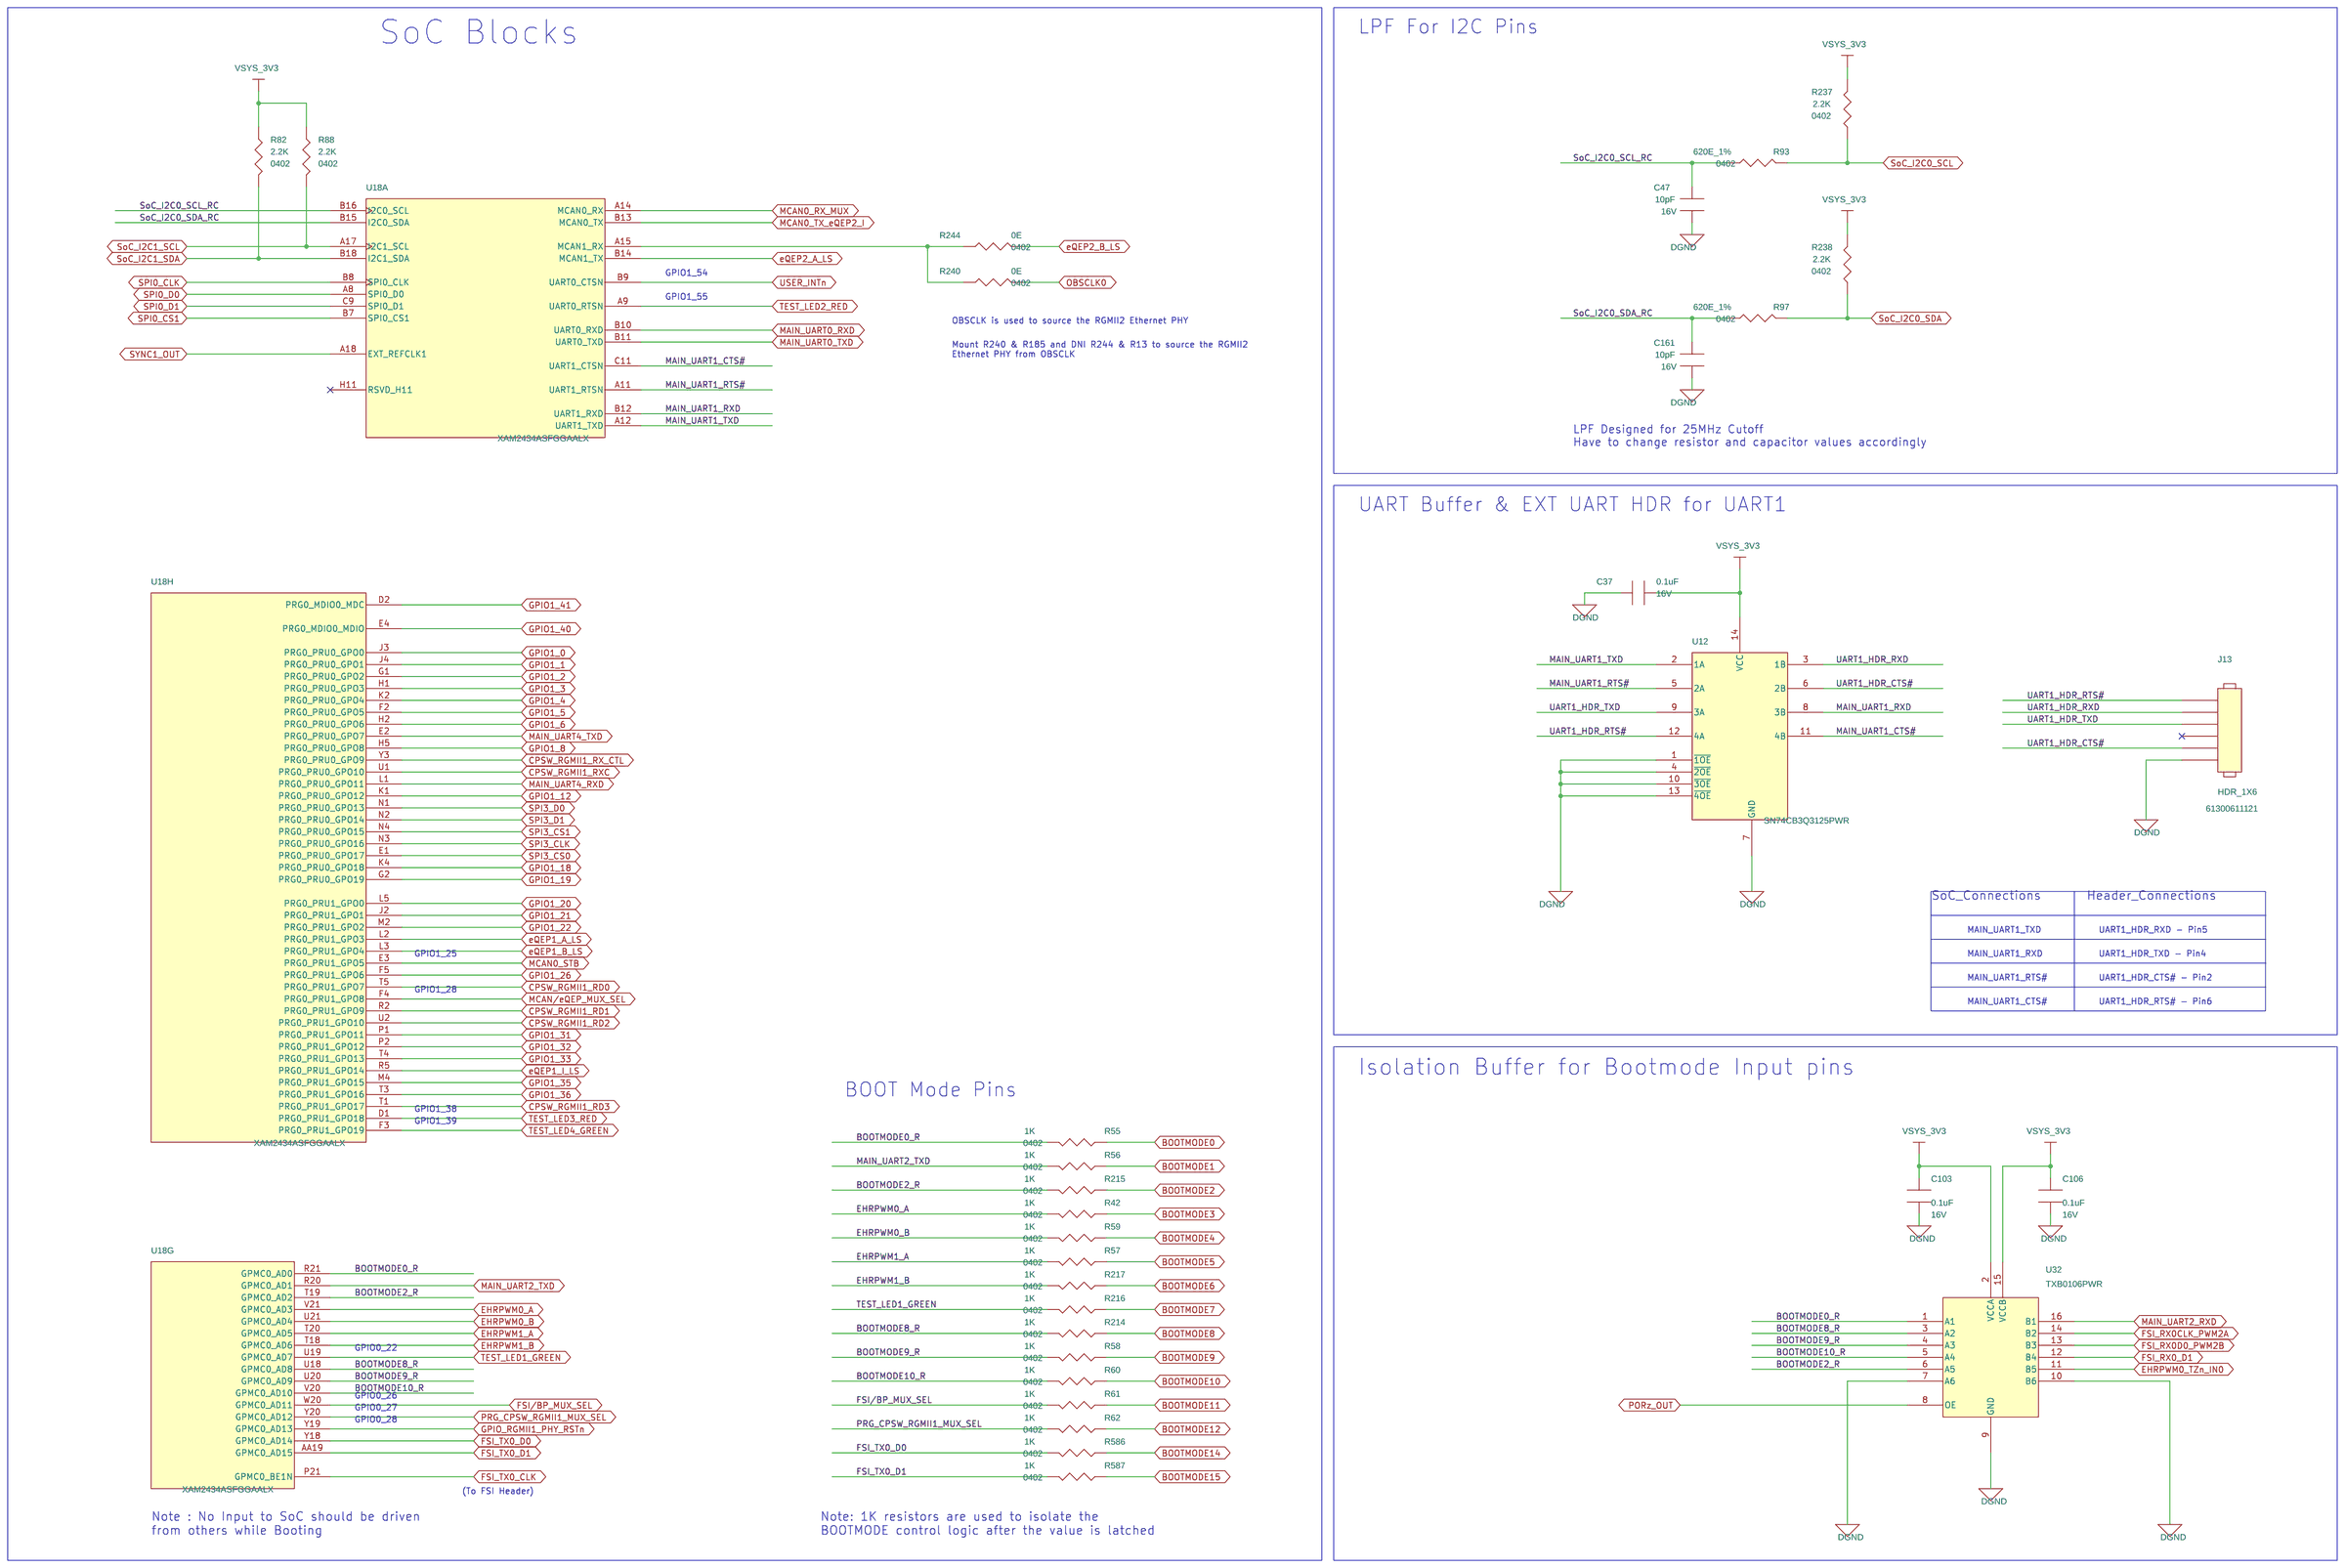
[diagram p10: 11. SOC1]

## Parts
sheet 10. RESET_INPUTs
C1  1uF  [CAP0201_0-5]
C2  1uF  [CAP0201_0-5]
C4  0.1uF  [CAP0201_0-5]
C29  0.1uF  [CAP0201_0-5]
C78  1uF  [CAP0201_0-5]
C79  1uF  [CAP0201_0-5]
C80  2400pF  [CAP0603_1]
C81  2400pF  [CAP0603_1]
C82  2400pF  [CAP0603_1]
C91  0.1uF  [CAP0201_0-5]
D1  TPD1E01B04DPLT  [DIO_DFN0201_0-4]
D2  TPD1E01B04DPLT  [DIO_DFN0201_0-4]
D4  TPD1E01B04DPLT  [DIO_DFN0201_0-4]
D5  TPD1E01B04DPLT  [DIO_DFN0201_0-4]
Q7  CSD25310Q2  [SON6_CSD17313Q2_80X80]
Q8  CSD25310Q2  [SON6_CSD17313Q2_80X80]
Q16  CSD25310Q2  [SON6_CSD17313Q2_80X80]
R1  1K  [RES0402_0-5]
R2  0E  [RES0402_0-5]
R3  10K  [RES0402_0-5]
R4  10K  [RES0402_0-5]
R6  12.7K_1%  [RES0402_0-5]
R8  0E  [RES0402_0-5]
R9  10K  [RES0402_0-5]
R11  10K  [RES0402_0-5]
R15  10K  [RES0402_0-5]
R164  1K  [RES0402_0-5]
R170  1K  [RES0402_0-5]
R171  1K  [RES0402_0-5]
R175  88.7K_1%  [RES0402_0-5]
R176  100K_1%  [RES0402_0-5]
R188  10K  [RES0402_0-5]
R195  14.7K_1%  [RES0402_0-5]
R198  16.9K_1%  [RES0402_0-5]
R199  5.23K_1%  [RES0402_0-5]
R201  100K_1%  [RES0402_0-5]
SW1  436331045822  [SW4_436331045822_190X190_SMD_1-7]
SW2  436331045822  [SW4_436331045822_190X190_SMD_1-7]
SW3  436331045822  [SW4_436331045822_190X190_SMD_1-7]
SW5  436331045822  [SW4_436331045822_190X190_SMD_1-7]
TP1  TP20_SMD  [TP20_SMD]
TP12  TP20_SMD  [TP20_SMD]
TP19  TP20_SMD  [TP20_SMD]
TP24  TP20_SMD  [TP20_SMD]
U1  SN74LVC1G11DCKR  [SC70-6]
U13  SN74LVC3G17DCUR  [VSSOP8_19-68_85X95_0-9]
U27  TPS386000RGPR  [QFN20_19-68_160X160_1]
sheet 11. SOC1
C37  0.1uF  [CAP0201_0-5]
C47  10pF  [CAP0402_0-75]
C103  0.1uF  [CAP0201_0-5]
C106  0.1uF  [CAP0201_0-5]
C161  10pF  [CAP0402_0-75]
J13  HDR_1X6  [HDR_1X6_61300611121_S_T_8-6]
R42  1K  [RES0402_0-5]
R55  1K  [RES0402_0-5]
R56  1K  [RES0402_0-5]
R57  1K  [RES0402_0-5]
R58  1K  [RES0402_0-5]
R59  1K  [RES0402_0-5]
R60  1K  [RES0402_0-5]
R61  1K  [RES0402_0-5]
R62  1K  [RES0402_0-5]
R82  2.2K  [RES0402_0-5]
R88  2.2K  [RES0402_0-5]
R93  620E_1%  [RES0402_0-5]
R97  620E_1%  [RES0402_0-5]
R214  1K  [RES0402_0-5]
R215  1K  [RES0402_0-5]
R216  1K  [RES0402_0-5]
R217  1K  [RES0402_0-5]
R237  2.2K  [RES0402_0-5]
R238  2.2K  [RES0402_0-5]
R240  0E  [RES0402_0-5]
R244  0E  [RES0402_0-5]
R586  1K  [RES0402_0-5]
R587  1K  [RES0402_0-5]
U12  SN74CB3Q3125PWR  [TSSOP14_25-59_205X180_1-2]
U32  TXB0106PWR  [TSSOP16_25-59_205X180]
sheet 25. SOC_ANALOG_POWER_DECAPs
U18  XAM2434ASFGGAALX  [BGA293_19-68_440X440_1]  (sections A,B,C,D,E,F,G,H,I,J,K,L,M)

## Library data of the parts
C1 C2 C78 C79 = CAP: CAP CERAMIC 1uF 16V 20% X5R 0201; Chkd/date: MANIRAJA/300520; Crtd /date: ALVY/260520; Custom_Duty: 15%; Customs_HS_Code: 85322990; Distributor_name: DIGIKEY; Distributor_part_number: 490-18654-1-ND; Footprint Path: Y:\MIS_DATABASE\Library\ALTIUM_TOOL\PCB_FOOTPRINTS\Altium_Footprint_Lib.PcbLib; Height: 0.39MM; Library Path: Y:\MIS_DATABASE\Library\ALTIUM_TOOL\SCHEMATICS_PARTS\MS_DISCRETE_Library.schlib; Mfr_name: MURATA; Mfr_part_number: GRM033R61C105ME15D; Mistral Part No: 120018090038-R; Package: 0201; Part_type: CAPACITORS\CERAMIC; Project: QCS610_NANOSOM; RoHS: RoHS; Temperature: -55°C+85°C; Tolerance: 20%; Voltage: 16V; Wattage: NA; Weight: 0.33mg; Datasheet: Y:\MIS_DATABASE\DATASHEETS\CAPACITORS\GRM033R61C105ME15.PDF
C4 C29 C37 C91 C103 C106 = CAP: CAP CERAMIC 0.1uF 16V 10% X5R 0201; Chkd/date: MANIRAJA/230118; Crtd /date: MANIRAJA/230118; Custom_Duty: 15%; Customs_HS_Code: 85322990; Distributor_name: DIGIKEY; Distributor_part_number: 490-14305-1-ND; Footprint Path: Y:\MIS_DATABASE\Library\ALTIUM_TOOL\PCB_FOOTPRINTS\Altium_Footprint_Lib.PcbLib; Height: 0.33MM; Library Path: Y:\MIS_DATABASE\Library\ALTIUM_TOOL\SCHEMATICS_PARTS\MS_DISCRETE_Library.schlib; Mfr_name: MURATA; Mfr_part_number: GRM033R61C104KE14D; Mistral Part No: 120009030072-R; Package: 0201; Part_type: CAPACITORS\CERAMIC; Project: TI_MAXIE_CPB; RoHS: RoHS; Temperature: -55°C+85°C; Tolerance: 10%; Voltage: 16V; Wattage: NA; Weight: 0.33mg; Datasheet: Y:\MIS_DATABASE\DATASHEETS\CAPACITORS\GRM033R61C104KE14.PDF
C80-C82 = CAP: CAP CERAMIC 2400pF 50V 5% C0G(NP0) 0603; Chkd/date: USMAN/231113; Crtd /date: USMAN/231113; Custom_Duty: 15%; Customs_HS_Code: 85322990; Distributor_name: DIGIKEY; Distributor_part_number: 490-3282-1-ND; Footprint Path: Y:\MIS_DATABASE\Library\ALTIUM_TOOL\PCB_FOOTPRINTS\Altium_Footprint_Lib.PcbLib; Height: 0.90MM; Library Path: Y:\MIS_DATABASE\Library\ALTIUM_TOOL\SCHEMATICS_PARTS\MS_DISCRETE_Library.schlib; Mfr_name: MURATA; Mfr_part_number: GRM1885C1H242JA01D; Mistral Part No: 120013110013-R; Package: 0603; Part_type: CAPACITORS\CERAMIC; Project: C-BAND_SYNTH; RoHS: RoHS; Temperature: -55°C+125°C; Tolerance: 5%; Voltage: 50V; Wattage: NA; Weight: 6.3mg; Datasheet: Y:\MIS_DATABASE\DATASHEETS\CAPACITORS\MURATA-GXX-SER_NOV17.PDF
D1 D2 D4 D5 = DIODE_TVS_DUAL: DIODE 1CH ESD PROTECTION FOR USB TYPE-C AND THUNDERBOLT3 X2SON2; Chkd/date: MANIRAJA/230920; Crtd /date: ALVY/230920; Custom_Duty: 15%; Customs_HS_Code: 85412900; Distributor_name: DIGIKEY; Distributor_part_number: 296-44484-1-ND; Footprint Path: Y:\MIS_DATABASE\Library\ALTIUM_TOOL\PCB_FOOTPRINTS\Altium_Footprint_Lib.PcbLib; Height: 0.32MM; Library Path: Y:\MIS_DATABASE\Library\ALTIUM_TOOL\SCHEMATICS_PARTS\MS_DISCRETE_Library.schlib; Mfr_name: TEXAS INSTRUMENTS; Mistral Part No: 130020090037-R; Package: X2SON2; Part_type: DIODE\TVS; Project: AM64X_SKEVM; RoHS: RoHS; Temperature: -40°C+125°C; Tolerance: NA; Voltage: NA; Wattage: NA; Weight: 0.2mg; Datasheet: Y:\MIS_DATABASE\DATASHEETS\DISCRETES\DIODES\TPD1E01B04.PDF
Q7 Q8 Q16 = MOSFET_CSD25310Q2: IC MOSFET P-CHANNEL WSON6; Chkd/date: VASANTHA/191215; Crtd /date: VASANTHA/191215; Custom_Duty: 15%; Customs_HS_Code: 85423100; Distributor_name: DIGIKEY; Distributor_part_number: 296-38915-1-ND; Height: 0.85MM; Mfr_name: TEXAS INSTRUMENTS; Mistral Part No: 142015120011-R; Package: WSON6; Part_type: ICS\POWER\MOSFET; Project: DUET BOARD; RoHS: RoHS; Temperature: -55°C+150°C; Tolerance: NA; Voltage: NA; Wattage: NA; Weight: NA; Datasheet: Y:\MIS_DATABASE\DATASHEETS\DISCRETES\TRANSISTORS_FETS\CSD25310Q2.PDF
R1 R42 R55-R62 R164 R170 R171 R214-R217 R586 R587 = RESISTOR: RES 1K 1/16W 5% 0402; Chkd/date: VASANTHA/120516; Crtd /date: VASANTHA/120516; Custom_Duty: 15%; Customs_HS_Code: 85332119; Distributor_name: DIGIKEY; Distributor_part_number: 311-1.0KJRCT-ND; Footprint Path: Y:\MIS_DATABASE\Library\ALTIUM_TOOL\PCB_FOOTPRINTS\Altium_Footprint_Lib.PcbLib; Height: 0.40MM; Library Path: Y:\MIS_DATABASE\Library\ALTIUM_TOOL\SCHEMATICS_PARTS\MS_DISCRETE_Library.schlib; Mfr_name: YAGEO AMERICA; Mfr_part_number: RC0402JR-071KL; Mistral Part No: 110010070006-R; Package: 0402; Part_type: RESISTORS\FIXED; Project: TMDXCSK368; RoHS: RoHS; Temperature: -55°C+155°C; Tolerance: 5%; Voltage: NA; Wattage: 1/16W; Weight: 0.65mg; Datasheet: Y:\MIS_DATABASE\DATASHEETS\RESISTORS\RCXXXXL-SER_MAR18.PDF
R2 R8 R240 R244 = RESISTOR: RES 0E 1/16W 5% 0402; Chkd/date: VASANTHA/291216; Crtd /date: CHAITHANYA/300911; Custom_Duty: 15%; Customs_HS_Code: 85332119; Distributor_name: DIGIKEY; Distributor_part_number: 311-0.0JRCT-ND; Footprint Path: Y:\MIS_DATABASE\Library\ALTIUM_TOOL\PCB_FOOTPRINTS\Altium_Footprint_Lib.PcbLib; Height: 0.40MM; Library Path: Y:\MIS_DATABASE\Library\ALTIUM_TOOL\SCHEMATICS_PARTS\MS_DISCRETE_Library.schlib; Mfr_name: YAGEO AMERICA; Mfr_part_number: RC0402JR-070RL; Mistral Part No: 110011090036-R; Package: 0402; Part_type: RESISTORS\FIXED; Project: VP-4000-PROCESSOR; RoHS: RoHS; Temperature: -55°C+155°C; Tolerance: 5%; Voltage: NA; Wattage: 1/16W; Weight: 0.65mg; Datasheet: Y:\MIS_DATABASE\DATASHEETS\RESISTORS\RCXXXXL-SER_MAR18.PDF
R3 R4 R9 R11 R15 R188 = RESISTOR: RES 10K 1/16W 5% 0402; Chkd/date: VASANTHA/061216; Crtd /date: MAZHAR/230805; Custom_Duty: 15%; Customs_HS_Code: 85332119; Distributor_name: DIGIKEY; Distributor_part_number: 311-10KJRCT-ND; Footprint Path: Y:\MIS_DATABASE\Library\ALTIUM_TOOL\PCB_FOOTPRINTS\Altium_Footprint_Lib.PcbLib; Height: 0.40MM; Library Path: Y:\MIS_DATABASE\Library\ALTIUM_TOOL\SCHEMATICS_PARTS\MS_DISCRETE_Library.schlib; Mfr_name: YAGEO AMERICA; Mfr_part_number: RC0402JR-0710KL; Mistral Part No: 110011060021-R; Package: 0402; Part_type: RESISTORS\FIXED; Project: HSE; RoHS: RoHS; Temperature: -55°C+155°C; Tolerance: 5%; Voltage: NA; Wattage: 1/16W; Weight: 0.65mg; Datasheet: Y:\MIS_DATABASE\DATASHEETS\RESISTORS\RCXXXXL-SER_MAR18.PDF
R6 = RESISTOR: RES 12.7K 1/10W 1% 0402; Chkd/date: MANIRAJA/280519; Crtd /date: ALVY/270519; Custom_Duty: 15%; Customs_HS_Code: 85332119; Distributor_name: DIGIKEY; Distributor_part_number: P12.7KLCT-ND; Footprint Path: Y:\MIS_DATABASE\Library\ALTIUM_TOOL\PCB_FOOTPRINTS\Altium_Footprint_Lib.PcbLib; Height: 0.40MM; Library Path: Y:\MIS_DATABASE\Library\ALTIUM_TOOL\SCHEMATICS_PARTS\MS_DISCRETE_Library.schlib; Mfr_name: PANASONIC-ECG; Mfr_part_number: ERJ-2RKF1272X; Mistral Part No: 110019050035-R; Package: 0402; Part_type: RESISTORS\FIXED; Project: BRUKER_SD820_COMMONDO; RoHS: RoHS; Temperature: -55°C+155°C; Tolerance: 1%; Voltage: NA; Wattage: 1/10W; Weight: 0.8mg; Datasheet: Y:\MIS_DATABASE\DATASHEETS\RESISTORS\PAN-ERJSER_NOV17.PDF
R175 = RESISTOR: RES 88.7K 1/16W 1% 0402; Chkd/date: MANIRAJA/130519; Crtd /date: ALVY/100519; Custom_Duty: 15%; Customs_HS_Code: 85332119; Distributor_name: DIGIKEY; Distributor_part_number: 311-88.7KLRCT-ND; Footprint Path: Y:\MIS_DATABASE\Library\ALTIUM_TOOL\PCB_FOOTPRINTS\Altium_Footprint_Lib.PcbLib; Height: 0.40MM; Library Path: Y:\MIS_DATABASE\Library\ALTIUM_TOOL\SCHEMATICS_PARTS\MS_DISCRETE_Library.schlib; Mfr_name: YAGEO AMERICA; Mfr_part_number: RC0402FR-0788K7L; Mistral Part No: 110011080015-R; Package: 0402; Part_type: RESISTORS\FIXED; Project: BRUKER_SD820_COMMONDO; RoHS: RoHS; Temperature: -55°C+155°C; Tolerance: 1%; Voltage: NA; Wattage: 1/16W; Weight: 0.65mg; Datasheet: Y:\MIS_DATABASE\DATASHEETS\RESISTORS\RCXXXXL-SER_MAR18.PDF
R176 R201 = RESISTOR: RES 100K 1/16W 1% 0402; Chkd/date: MANIRAJA/110917; Crtd /date: MANIRAJA/110917; Custom_Duty: 15%; Customs_HS_Code: 85332119; Distributor_name: DIGIKEY; Distributor_part_number: 311-100KLRCT-ND; Footprint Path: Y:\MIS_DATABASE\Library\ALTIUM_TOOL\PCB_FOOTPRINTS\Altium_Footprint_Lib.PcbLib; Height: 0.40MM; Library Path: Y:\MIS_DATABASE\Library\ALTIUM_TOOL\SCHEMATICS_PARTS\MS_DISCRETE_Library.schlib; Mfr_name: YAGEO AMERICA; Mfr_part_number: RC0402FR-07100KL; Mistral Part No: 110014060043-R; Package: 0402; Part_type: RESISTORS\FIXED; Project: CRADE RF CARD; RoHS: RoHS; Temperature: -55°C+155°C; Tolerance: 1%; Voltage: NA; Wattage: 1/16W; Weight: 0.65mg; Datasheet: Y:\MIS_DATABASE\DATASHEETS\RESISTORS\RCXXXXL-SER_MAR18.PDF
R195 = RESISTOR: RES 14.7K 1/10W 1% 0402; Chkd/date: SUHAS/270910; Crtd /date: MAZHAR/241109; Custom_Duty: 15%; Customs_HS_Code: 85332119; Distributor_name: DIGIKEY; Distributor_part_number: P14.7KLCT-ND; Footprint Path: Y:\MIS_DATABASE\Library\ALTIUM_TOOL\PCB_FOOTPRINTS\Altium_Footprint_Lib.PcbLib; Height: 0.40MM; Library Path: Y:\MIS_DATABASE\Library\ALTIUM_TOOL\SCHEMATICS_PARTS\MS_DISCRETE_Library.schlib; Mfr_name: PANASONIC-ECG; Mfr_part_number: ERJ-2RKF1472X; Mistral Part No: 110009110010-R; Package: 0402; Part_type: RESISTORS\FIXED; Project: GOLDEN-I; RoHS: RoHS; Temperature: -55°C+155°C; Tolerance: 1%; Voltage: NA; Wattage: 1/10W; Weight: 0.8mg; Datasheet: Y:\MIS_DATABASE\DATASHEETS\RESISTORS\PAN-ERJSER_NOV17.PDF
R198 = RESISTOR: RES 16.9K 1/16W 1% 0402; Chkd/date: MANIRAJA/280920; Crtd /date: ALVY/250920; Custom_Duty: 15%; Customs_HS_Code: 85332119; Distributor_name: DIGIKEY; Distributor_part_number: YAG3003CT-ND; Footprint Path: Y:\MIS_DATABASE\Library\ALTIUM_TOOL\PCB_FOOTPRINTS\Altium_Footprint_Lib.PcbLib; Height: 0.40MM; Library Path: Y:\MIS_DATABASE\Library\ALTIUM_TOOL\SCHEMATICS_PARTS\MS_DISCRETE_Library.schlib; Mfr_name: YAGEO AMERICA; Mfr_part_number: RC0402FR-0716K9L; Mistral Part No: 110020090010-R; Package: 0402; Part_type: RESISTORS\FIXED; Project: TI_J7ES_CP; RoHS: RoHS; Temperature: -55°C+155°C; Tolerance: 1%; Voltage: NA; Wattage: 1/16W; Weight: 12mg; Datasheet: Y:\MIS_DATABASE\DATASHEETS\RESISTORS\RCXXXXL-SER_MAR18.PDF
R199 = RESISTOR: RES 5.23K 1/16W 1% 0402; Chkd/date: JEBRAN/110815; Crtd /date: JEBRAN/110815; Custom_Duty: 15%; Customs_HS_Code: 85332119; Distributor_name: DIGIKEY; Distributor_part_number: 541-5.23KLCT-ND; Footprint Path: Y:\MIS_DATABASE\Library\ALTIUM_TOOL\PCB_FOOTPRINTS\Altium_Footprint_Lib.PcbLib; Height: 0.40MM; Library Path: Y:\MIS_DATABASE\Library\ALTIUM_TOOL\SCHEMATICS_PARTS\MS_DISCRETE_Library.schlib; Mfr_name: VISHAY; Mfr_part_number: CRCW04025K23FKED; Mistral Part No: 110015080018-R; Package: 0402; Part_type: RESISTORS\FIXED; Project: OCTASIC_3000; RoHS: RoHS; Temperature: -55°C+155°C; Tolerance: 1%; Voltage: NA; Wattage: 1/16W; Weight: 0.65mg; Datasheet: Y:\MIS_DATABASE\DATASHEETS\RESISTORS\CRCW0603.PDF
SW1-SW3 SW5 = SW4_EVQP: SWITCH TACTILE SPST RT SMD; Chkd/date: MANIRAJA/051020; Crtd /date: ALVY/011020; Custom_Duty: 24%; Customs_HS_Code: 85369090; Distributor_name: DIGIKEY; Distributor_part_number: 732-7059-1-ND; Footprint Path: Y:\MIS_DATABASE\Library\ALTIUM_TOOL\PCB_FOOTPRINTS\Altium_Footprint_Lib.PcbLib; Height: 1.65MM; Library Path: Y:\MIS_DATABASE\Library\ALTIUM_TOOL\SCHEMATICS_PARTS\MS_SWITCH_Library.schlib; Mfr_name: WURTH ELECTRONICS; Mistral Part No: 130020100002-R; Package: SMD; Part_type: ELECTRO-MECHANICAL\SWITCH; Project: AM64X_SKEVM; RoHS: RoHS; Temperature: -40°C+85°C; Tolerance: NA; Voltage: NA; Wattage: NA; Weight: 50mg; Datasheet: Y:\MIS_DATABASE\DATASHEETS\MISC\SWITCHES\436331045822.PDF
TP1 TP12 TP19 TP24 = TESTPOINT: TESTPOINT CIR 20 SMD; Chkd/date: SHREESHAIL/171006; Crtd /date: MAZHAR/171006; Custom_Duty: NA; Customs_HS_Code: NA; Distributor_name: NA; Distributor_part_number: NA; Footprint Path: Y:\MIS_DATABASE\Library\ALTIUM_TOOL\PCB_FOOTPRINTS\Altium_Footprint_Lib.PcbLib; Height: NA; Library Path: Y:\MIS_DATABASE\Library\ALTIUM_TOOL\SCHEMATICS_PARTS\MS_DISCRETE_Library.schlib; MECHANICAL 3D STEP FILE: NA; Mfr_name: LOCAL; Mistral Part No: NA; Package: SMD; Project: BT MODULE_CSRBC04; RoHS: NA; Temperature: NA; Tolerance: NA; Voltage: NA; Wattage: NA; Weight: NA; Datasheet: NA
U1 = SN74LVC1G11DCKR_SC70-6: IC SINGLE 3-INPUT POSITIVE-AND GATE SC70-6; Chkd/date: SHREESHAIL/220506; Crtd /date: MAZHAR/150506; Custom_Duty: 15%; Customs_HS_Code: 85423100; Distributor_name: DIGIKEY; Distributor_part_number: 296-18066-1-ND; Height: 1.10MM; Mfr_name: TEXAS INSTRUMENTS; Mistral Part No: 141009030230-R; Part_type: ICS\DIGITAL\GATES; Project: VOCERA; RoHS: Sb/ Br FREE; Datasheet: Y:\MIS_DATABASE\DATASHEETS\ICS\DIGITAL\GATES\SN74LVC1G.PDF
U13 = SN74LVC3G17DCUR_VSSOP8: IC TRIPLE SCHMITT-TRIGGER BUFFER VSSOP8; Chkd/date: MANIRAJA/280917; Crtd /date: MANIRAJA/280917; Custom_Duty: 15%; Customs_HS_Code: 85423100; Distributor_name: DIGIKEY; Distributor_part_number: 296-18818-1-ND; Height: 0.90MM; Mfr_name: TEXAS INSTRUMENTS; Mistral Part No: 141017090019-R; Package: VSSOP8; Part_type: ICS\DIGITAL\COMBINATIONAL; Project: TI_MAXIE_CPB; RoHS: RoHS; Temperature: -40°C+125°C; Tolerance: NA; Voltage: NA; Wattage: NA; Weight: 9.6mg; Datasheet: Y:\MIS_DATABASE\DATASHEETS\ICS\DIGITAL\COMBINATIONAL\SN74LVC3G17.PDF
U27 = TPS386000RGPR_QFN20: IC QUAD SUPPLY SUPERVISORS WITH ADJ DELAY & WATCHDOG TIMER QFN20; Chkd/date: VASANTHA/230117; Crtd /date: MANIRAJA/230117; Custom_Duty: 15%; Customs_HS_Code: 85423100; Distributor_name: DIGIKEY; Distributor_part_number: 296-39392-1-ND; Height: 1.00MM; Mfr_name: TEXAS INSTRUMENTS; Mistral Part No: 142017010013-R; Package: QFN20; Part_type: ICS\POWER; Project: CRADE-CONTROLLER CARD; RoHS: RoHS; Temperature: -40°C+125°C; Tolerance: NA; Voltage: NA; Wattage: NA; Weight: 70mg; Datasheet: Y:\MIS_DATABASE\DATASHEETS\ICS\POWER\TPS3860.PDF
C47 C161 = CAP: CAP CERAMIC 10pF 16V 5% C0G(NP0) 0402; Chkd/date: MANIRAJA/100918; Crtd /date: ALVY/100918; Custom_Duty: 15%; Customs_HS_Code: 85322990; Distributor_name: DIGIKEY; Distributor_part_number: 732-7441-1-ND; Footprint Path: Y:\MIS_DATABASE\Library\ALTIUM_TOOL\PCB_FOOTPRINTS\Altium_Footprint_Lib.PcbLib; Height: 0.55MM; Library Path: Y:\MIS_DATABASE\Library\ALTIUM_TOOL\SCHEMATICS_PARTS\MS_DISCRETE_Library.schlib; Mfr_name: WURTH ELECTRONICS; Mfr_part_number: 885012005025; Mistral Part No: 120018030015-R; Package: 0402; Part_type: CAPACITORS\CERAMIC; Project: SMART-M_SCRIPTALK_PB; RoHS: RoHS; Temperature: -55°C+125°C; Tolerance: 5%; Voltage: 16V; Wattage: NA; Weight: 0.65mg; Datasheet: Y:\MIS_DATABASE\DATASHEETS\CAPACITORS\885012005025.PDF
J13 = HEADER_6X1: CON HDR 1X6 2.54MM PITCH ST TH; Chkd/date: MANIRAJA/161219; Crtd /date: MANIRAJA/161219; Custom_Duty: 24%; Customs_HS_Code: 85369090; Distributor_name: DIGIKEY; Distributor_part_number: 732-5319-ND; Footprint Path: Y:\MIS_DATABASE\Library\ALTIUM_TOOL\PCB_FOOTPRINTS\Altium_Footprint_Lib.PcbLib; Height: 8.54MM; Library Path: Y:\MIS_DATABASE\Library\ALTIUM_TOOL\SCHEMATICS_PARTS\MS_CONNECTOR_Library.schlib; Mfr_name: WURTH ELECTRONICS; Mfr_part_number: 61300611121; Mistral Part No: 150019120017-R; Package: THRU-HOLE; Part_type: CONNECTOR\HEADERS; Project: SD820_NANOSOM_TESTJIG; RoHS: RoHS; Temperature: -40°C+105°C; Tolerance: NA; Voltage: NA; Wattage: NA; Weight: 342.4mg; Datasheet: Y:\MIS_DATABASE\DATASHEETS\CONNECTORS\6130XXX.PDF
R82 R88 R237 R238 = RESISTOR: RES 2.2K 1/16W 5% 0402; Chkd/date: VASANTHA/061216; Crtd /date: BAVISH/021210; Custom_Duty: 15%; Customs_HS_Code: 85332119; Distributor_name: DIGIKEY; Distributor_part_number: 311-2.2KJRCT-ND; Footprint Path: Y:\MIS_DATABASE\Library\ALTIUM_TOOL\PCB_FOOTPRINTS\Altium_Footprint_Lib.PcbLib; Height: 0.40MM; Library Path: Y:\MIS_DATABASE\Library\ALTIUM_TOOL\SCHEMATICS_PARTS\MS_DISCRETE_Library.schlib; Mfr_name: YAGEO AMERICA; Mfr_part_number: RC0402JR-072K2L; Mistral Part No: 110010120018-R; Package: 0402; Part_type: RESISTORS\FIXED; Project: TE4; RoHS: RoHS; Temperature: -55°C+155°C; Tolerance: 5%; Voltage: NA; Wattage: 1/16W; Weight: 0.65mg; Datasheet: Y:\MIS_DATABASE\DATASHEETS\RESISTORS\RCXXXXL-SER_MAR18.PDF
R93 R97 = RESISTOR: RES 620E 1/16W 1% 0402; Chkd/date: ALVY/091220; Crtd /date: MANIRAJA/091220; Custom_Duty: 15%; Customs_HS_Code: 85332119; Distributor_name: DIGIKEY; Distributor_part_number: 311-620LRCT-ND; Footprint Path: Y:\MIS_DATABASE\Library\ALTIUM_TOOL\PCB_FOOTPRINTS\Altium_Footprint_Lib.PcbLib; Height: 0.40MM; Library Path: Y:\MIS_DATABASE\Library\ALTIUM_TOOL\SCHEMATICS_PARTS\MS_DISCRETE_Library.schlib; Mfr_name: YAGEO AMERICA; Mfr_part_number: RC0402FR-07620RL; Mistral Part No: 110020120009-R; Package: 0402; Part_type: RESISTORS\FIXED; Project: TI_AM243x LP EVM; RoHS: RoHS; Temperature: -55°C+155°C; Tolerance: 1%; Voltage: NA; Wattage: 1/16W; Weight: 0.65mg; Datasheet: Y:\MIS_DATABASE\DATASHEETS\RESISTORS\RCXXXXL-SER_MAR18.PDF
U12 = SN74CBTLV3125PWR_TSSOP14: IC 2.5/3.3V QUADRUPLE HIGH-BANDWIDTH FET BUS SWITCH TSSOP14; Chkd/date: MANIRAJA/241018; Crtd /date: ALVY/241018; Custom_Duty: 15%; Customs_HS_Code: 85423100; Distributor_name: DIGIKEY; Distributor_part_number: 296-16804-1-ND; Footprint Path: Y:\MIS_DATABASE\Library\ALTIUM_TOOL\PCB_FOOTPRINTS\Altium_Footprint_Lib.PcbLib; Height: 1.20MM; Library Path: Y:\MIS_DATABASE\Library\ALTIUM_TOOL\SCHEMATICS_PARTS\MS_COMBINATIONAL_Library.schlib; Mfr_name: TEXAS INSTRUMENTS; Mistral Part No: 141018100021-R; Package: TSSOP14; Part_type: ICS\DIGITAL\COMBINATIONAL; Project: TI_J7ES_EVM_CP; RoHS: RoHS; Temperature: -40°C+85°C; Tolerance: NA; Voltage: NA; Wattage: NA; Weight: 57.2mg; Datasheet: Y:\MIS_DATABASE\DATASHEETS\ICS\DIGITAL\COMBINATIONAL\SN74CB3Q3125.PDF
U32 = TXB0106PWR_TSSOP16: IC VOLTAGE-LEVEL TRANSLATOR 6-BIT BIDIRECTIONAL TSSOP16; Chkd/date: NAVEED/130415; Crtd /date: JEBRAN/090415; Custom_Duty: 15%; Customs_HS_Code: 85423100; Distributor_name: DIGIKEY; Distributor_part_number: 296-23759-1-ND; Height: 1.20MM; Mfr_name: TEXAS INSTRUMENTS; Mistral Part No: 141015040006-R; Package: TSSOP16; Part_type: ICS\INTERFACE\LEVEL TRANSLATOR; Project: GALILEO; RoHS: RoHS; Temperature: -40°C+85°C; Tolerance: NA; Voltage: NA; Wattage: NA; Weight: NA; Datasheet: Y:\MIS_DATABASE\DATASHEETS\ICS\INTERFACE\TXB0106PWR.PDF
U18 = AM243X_SOC_LP_EVM_BGA293: IC AM243x SoC_LP_EVM MICROPROCESSOR BGA293; Chkd/date: MANIRAJA/131120; Crtd /date: ALVY/121120; Custom_Duty: 15%; Customs_HS_Code: 85423100; Distributor_name: NA; Distributor_part_number: NA; Footprint Path: Y:\MIS_DATABASE\Library\ALTIUM_TOOL\PCB_FOOTPRINTS\Altium_Footprint_Lib.PcbLib; Height: 1.00MM; Library Path: Y:\MIS_DATABASE\Library\ALTIUM_TOOL\SCHEMATICS_PARTS\MS_MICROPROCESSOR_Library.schlib; Library Ref: AM243x SoC_LP_EVM_BGA293; Mfr_name: TEXAS INSTRUMENTS; Mistral Part No: 141220110003; Package: BGA293; Part_type: ICS\DIGITAL\MICROPROCESSOR; Project: TI_AM243x LP EVM; RoHS: NA; Temperature: NA; Tolerance: NA; Voltage: NA; Wattage: NA; Weight: NA; Datasheet: Y:\MIS_DATABASE\DATASHEETS\ICS\DIGITAL\MICROCONTROLLER\AM243x SoC-FP.PDF

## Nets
DGND: C1.2 C2.2 C4.2 C29.2 C37.2 C47.2 C78.2 C79.2 C80.2 C81.2 C82.2 C91.2 C103.2 C106.2 C161.2 D1.2(ANODE) D2.2(ANODE) D4.2(ANODE) D5.2(ANODE) J13.1 Q7.4(D1) Q7.7(D2) Q8.4(D1) Q8.7(D2) Q16.4(D1) Q16.7(D2) R9.1 R175.1 R195.2 R199.2 SW1.2 SW1.4 SW2.2 SW2.4 SW3.2 SW3.4 SW5.2 SW5.4 U1.2(GND) U12.1(~{1OE}) U12.4(~{2OE}) U12.7(GND) U12.10(~{3OE}) U12.13(~{4OE}) U13.4(GND) U27.12(GND) U27.21(EP) U32.7(A6) U32.9(GND) U32.10(B6) ; also on sheet 12 13 14 15 16 17 18 19 20 21 22 23 24 25 26 27 28
VDD_1V8: R198.1 ; also on sheet 12 25 28
VDD_1V8_CT: C80.1 U27.5(CT1)
VDD_1V8_SENSE: R198.2 R199.1 U27.10(SENSE1)
VDD_CORE_0V85: R176.2 ; also on sheet 24 25 27
VDD_CORE_0V85_H_SENSE: R6.1 R175.2 U27.6(SENSE4H)
VDD_CORE_0V85_L_SENSE: R6.2 R176.1 U27.7(SENSE4L)
VDDA_1V8: C4.1 R15.2 U1.5(VCC) ; also on sheet 25
BOOTMODE0: R55.2 ; also on sheet 21
BOOTMODE0_R: R55.1 U18.R21(GPMC0_AD0) U32.1(A1)
BOOTMODE1: R56.2 ; also on sheet 21
BOOTMODE2: R215.2 ; also on sheet 21
BOOTMODE2_R: R215.1 U18.T19(GPMC0_AD2) U32.6(A5)
BOOTMODE3: R42.2 ; also on sheet 21
BOOTMODE4: R59.2 ; also on sheet 21
BOOTMODE5: R57.2 ; also on sheet 21
BOOTMODE6: R217.2 ; also on sheet 21
BOOTMODE7: R216.2 ; also on sheet 21
BOOTMODE8: R214.2 ; also on sheet 21
BOOTMODE8_R: R214.1 U18.U18(GPMC0_AD8) U32.3(A2)
BOOTMODE9: R58.2 ; also on sheet 21
BOOTMODE9_R: R58.1 U18.U20(GPMC0_AD9) U32.4(A3)
BOOTMODE10: R60.2 ; also on sheet 21
BOOTMODE10_R: R60.1 U18.V20(GPMC0_AD10) U32.5(A4)
BOOTMODE11: R61.2 ; also on sheet 21
BOOTMODE12: R62.2 ; also on sheet 21
BOOTMODE14: R586.2 ; also on sheet 21
BOOTMODE15: R587.2 ; also on sheet 21
BP_CONN_1_PORz: R8.1 ; also on sheet 19
BP_CONN_2_PORz: R2.1 ; also on sheet 19
CORE_0V85_CT: C82.1 U27.2(CT4)
CPSW_RGMII1_RD0: U18.T5(PRG0_PRU1_GPO7) ; also on sheet 16
CPSW_RGMII1_RD1: U18.R2(PRG0_PRU1_GPO9) ; also on sheet 16
CPSW_RGMII1_RD2: U18.U2(PRG0_PRU1_GPO10) ; also on sheet 16
CPSW_RGMII1_RD3: U18.T1(PRG0_PRU1_GPO17) ; also on sheet 16
CPSW_RGMII1_RX_CTL: U18.Y3(PRG0_PRU0_GPO9) ; also on sheet 16
CPSW_RGMII1_RXC: U18.U1(PRG0_PRU0_GPO10) ; also on sheet 16
Debounce_MCU_RESETz: C1.1 D1.1(CATHODE) R1.1 SW2.1 SW2.3 U13.1(1A)
Debounce_SoC_RESET_REQz: C2.1 D2.1(CATHODE) Q7.1(S1) Q7.2(S2) Q7.5(S3) Q7.6(S4) Q7.8(S5) R170.1 SW3.1 SW3.3 U13.6(3A)
Debounce_USER_INTn: C78.1 D4.1(CATHODE) Q16.1(S1) Q16.2(S2) Q16.5(S3) Q16.6(S4) Q16.8(S5) R164.1 SW5.1 SW5.3 U13.3(2A)
EHRPWM0_A: R42.1 U18.V21(GPMC0_AD3) ; also on sheet 19
EHRPWM0_B: R59.1 U18.U21(GPMC0_AD4) ; also on sheet 19
EHRPWM0_TZn_IN0: U32.11(B5) ; also on sheet 19
EHRPWM1_A: R57.1 U18.T20(GPMC0_AD5) ; also on sheet 19
EHRPWM1_B: R217.1 U18.T18(GPMC0_AD6) ; also on sheet 19
eQEP1_A_LS: U18.L2(PRG0_PRU1_GPO3) ; also on sheet 13
eQEP1_B_LS: U18.L3(PRG0_PRU1_GPO4) ; also on sheet 13
eQEP1_I_LS: U18.R5(PRG0_PRU1_GPO14) ; also on sheet 13
eQEP2_A_LS: U18.B14(MCAN1_TX) ; also on sheet 13
eQEP2_B_LS: R244.2 ; also on sheet 13
FSI/BP_MUX_SEL: R61.1 U18.W20(GPMC0_AD11) ; also on sheet 13
FSI_RX0_D1: U32.12(B4) ; also on sheet 14
FSI_RX0CLK_PWM2A: U32.14(B2) ; also on sheet 13
FSI_RX0D0_PWM2B: U32.13(B3) ; also on sheet 13
FSI_TX0_CLK: U18.P21(GPMC0_BE1N) ; also on sheet 14
FSI_TX0_D0: R586.1 U18.Y18(GPMC0_AD14) ; also on sheet 14
FSI_TX0_D1: R587.1 U18.AA19(GPMC0_AD15) ; also on sheet 14
GPIO1_0: U18.J3(PRG0_PRU0_GPO0) ; also on sheet 19
GPIO1_1: U18.J4(PRG0_PRU0_GPO1) ; also on sheet 19
GPIO1_2: U18.G1(PRG0_PRU0_GPO2) ; also on sheet 19
GPIO1_3: U18.H1(PRG0_PRU0_GPO3) ; also on sheet 19
GPIO1_4: U18.K2(PRG0_PRU0_GPO4) ; also on sheet 19
GPIO1_5: U18.F2(PRG0_PRU0_GPO5) ; also on sheet 19
GPIO1_6: U18.H2(PRG0_PRU0_GPO6) ; also on sheet 19
GPIO1_8: U18.H5(PRG0_PRU0_GPO8) ; also on sheet 19
GPIO1_12: U18.K1(PRG0_PRU0_GPO12) ; also on sheet 19
GPIO1_18: U18.K4(PRG0_PRU0_GPO18) ; also on sheet 19
GPIO1_19: U18.G2(PRG0_PRU0_GPO19) ; also on sheet 19
GPIO1_20: U18.L5(PRG0_PRU1_GPO0) ; also on sheet 19
GPIO1_21: U18.J2(PRG0_PRU1_GPO1) ; also on sheet 19
GPIO1_22: U18.M2(PRG0_PRU1_GPO2) ; also on sheet 19
GPIO1_26: U18.F5(PRG0_PRU1_GPO6) ; also on sheet 19
GPIO1_31: U18.P1(PRG0_PRU1_GPO11) ; also on sheet 19
GPIO1_32: U18.P2(PRG0_PRU1_GPO12) ; also on sheet 19
GPIO1_33: U18.T4(PRG0_PRU1_GPO13) ; also on sheet 19
GPIO1_35: U18.M4(PRG0_PRU1_GPO15) ; also on sheet 19
GPIO1_36: U18.T3(PRG0_PRU1_GPO16) ; also on sheet 19
GPIO1_40: U18.E4(PRG0_MDIO0_MDIO) ; also on sheet 19
GPIO1_41: U18.D2(PRG0_MDIO0_MDC) ; also on sheet 19
GPIO_RGMII1_PHY_RSTn: U18.Y19(GPMC0_AD13) ; also on sheet 17
MAIN_UART0_RXD: U18.B10(UART0_RXD) ; also on sheet 22
MAIN_UART0_TXD: U18.B11(UART0_TXD) ; also on sheet 22
MAIN_UART1_CTS#: U12.11(4B) U18.C11(UART1_CTSN)
MAIN_UART1_RTS#: U12.5(2A) U18.A11(UART1_RTSN)
MAIN_UART1_RXD: U12.8(3B) U18.B12(UART1_RXD)
MAIN_UART1_TXD: U12.2(1A) U18.A12(UART1_TXD)
MAIN_UART2_RXD: U32.16(B1) ; also on sheet 19
MAIN_UART2_TXD: R56.1 U18.R20(GPMC0_AD1) ; also on sheet 19
MAIN_UART4_RXD: U18.L1(PRG0_PRU0_GPO11) ; also on sheet 19
MAIN_UART4_TXD: U18.E2(PRG0_PRU0_GPO7) ; also on sheet 19
MCAN0_RX_MUX: U18.A14(MCAN0_RX) ; also on sheet 13
MCAN0_STB: U18.E3(PRG0_PRU1_GPO5) ; also on sheet 14
MCAN0_TX_eQEP2_I: U18.B13(MCAN0_TX) ; also on sheet 13
MCAN/eQEP_MUX_SEL: U18.F4(PRG0_PRU1_GPO8) ; also on sheet 13
MCU_PORz: TP1.1(TP) U1.4(Y) ; also on sheet 12
MCU_RESETz: TP19.1(TP) U13.7(1Y) ; also on sheet 12
OBSCLK0: R240.2 ; also on sheet 18
PORZ_OUT: U32.8(OE) ; also on sheet 12 15 17 18 21
PRG_CPSW_RGMII1_MUX_SEL: R62.1 U18.Y20(GPMC0_AD12) ; also on sheet 16
R_BP_CONN_1_PORz: R4.1 R8.2 U1.3(B)
R_BP_CONN_2_PORz: R2.2 R3.1 U1.6(C)
SENCE3_IP: R188.2 U27.8(SENSE3)
SoC_I2C0_SCL: R93.1 R237.2 ; also on sheet 15 19 23
SoC_I2C0_SCL_RC: C47.1 R93.2 U18.B16(I2C0_SCL)
SoC_I2C0_SDA: R97.1 R238.2 ; also on sheet 15 19 23
SoC_I2C0_SDA_RC: C161.1 R97.2 U18.B15(I2C0_SDA)
SoC_I2C1_SCL: R88.2 U18.A17(I2C1_SCL) ; also on sheet 19 20
SoC_I2C1_SDA: R82.2 U18.B18(I2C1_SDA) ; also on sheet 19 20
SoC_RESET_REQz: TP24.1(TP) U13.2(3Y) ; also on sheet 12
SPI0_CLK: U18.B8(SPI0_CLK) ; also on sheet 19
SPI0_CS1: U18.B7(SPI0_CS1) ; also on sheet 19
SPI0_D0: U18.A8(SPI0_D0) ; also on sheet 19
SPI0_D1: U18.C9(SPI0_D1) ; also on sheet 19
SPI3_CLK: U18.N3(PRG0_PRU0_GPO16) ; also on sheet 19
SPI3_CS0: U18.E1(PRG0_PRU0_GPO17) ; also on sheet 19
SPI3_CS1: U18.N4(PRG0_PRU0_GPO15) ; also on sheet 19
SPI3_D0: U18.N1(PRG0_PRU0_GPO13) ; also on sheet 19
SPI3_D1: U18.N2(PRG0_PRU0_GPO14) ; also on sheet 19
SYNC1_OUT: U18.A18(EXT_REFCLK1) ; also on sheet 19
TA_PORZn: Q8.3(G) ; also on sheet 20
TA_SOC_INTn: Q16.3(G) ; also on sheet 20
TA_WARMRESETn: Q7.3(G) ; also on sheet 20
TEST_LED1_GREEN: R216.1 U18.U19(GPMC0_AD7) ; also on sheet 23
TEST_LED2_RED: U18.A9(UART0_RTSN) ; also on sheet 23
TEST_LED3_RED: U18.D1(PRG0_PRU1_GPO18) ; also on sheet 23
TEST_LED4_GREEN: U18.F3(PRG0_PRU1_GPO19) ; also on sheet 23
UART1_HDR_CTS#: J13.2 U12.6(2B)
UART1_HDR_RTS#: J13.6 U12.12(4A)
UART1_HDR_RXD: J13.5 U12.3(1B)
UART1_HDR_TXD: J13.4 U12.9(3A)
USER_INTn: TP12.1(TP) U13.5(2Y) U18.B9(UART0_CTSN)
VMON_MRn: C79.1 D5.1(CATHODE) Q8.1(S1) Q8.2(S2) Q8.5(S3) Q8.6(S4) Q8.8(S5) R171.1 SW1.1 SW1.3 U27.1(~{MR})
VSYS_3V3: C29.1 C37.1 C103.1 C106.1 R1.2 R3.2 R4.2 R82.1 R88.1 R164.2 R170.2 R201.2 R237.1 R238.1 U12.14(VCC) U13.8(VCC) U32.2(VCCA) U32.15(VCCB) ; also on sheet 12 13 14 15 16 17 18 19 20 21 22 23 24 25 27 28
VSYS_3V3_CT: C81.1 U27.4(CT2)
VSYS_3V3_SENSE: R195.1 R201.1 U27.9(SENSE2)
VSYS_5V0: C91.1 R11.1 R171.2 R188.1 U27.14(VDD) ; also on sheet 13 14 19 20 25 26 27 28
WDI: R9.2 U27.20(WDI)
WDO: R11.2 U27.19(WDO)
N30339679: R15.1 U1.1(A) U27.15(~{RESET1}) U27.16(~{RESET2}) U27.18(~{RESET4})
N30900913: R240.1 R244.1 U18.A15(MCAN1_RX)

Not connected (* = marked no-connect by the designer): J13 3*; U18 H11(RSVD)*; U27 3(CT3)* 11(NC)* 13(VREF)* 17(~{RESET3})*

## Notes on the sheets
sheet 1
- REVISION HISTORY
- VER #
- DATE
- DESCRIPTION OF CHANGES
- AUTHOR
- REVIEWED  BY
- APPROVED  BY
- 0.1
- 10th AUG 2021
- Drafted from PROC109E2 v1.0
- Mistral Design Team
- 1. RJ45 Connector's J18 and J19  Mfr. Part No. changed from 7499111614A (Wurth Electronics)  to
  LPJG16314A4NL (Link-PP) with common center tap. Removed the capacitors C164, C195, C261, C264,
  C83, C89, C115 & C127
  2. Ethernet PHY1(U19) RX link indication signal "PRG1_CPSW_ETH1_LED_LINK" is connected to SoC
  GPIO signal "PRG1_PRU0_GPO8 ". VPP_1V8_REG_EN signal from SoC GPIO Signal PRG1_PRU0_GPO8 is
  removed.
  Added Pull UP resisitor (R593) and 2x1 (J22) header for enable option of VPP supply.
  3. Ethernet PHY2 (U7) RX link indication Signal  "PRG1_CPSW_ETH2_LED_LINK" is connected to SoC
  GPIO signal "PRG1_PRU1_GPO8".  And the net "GPIO_RGMII1_PHY_RSTn" is moved to GPMC0_AD11.
  USER_LED1 ciricuit (R18, R38, Q2 & LD5) is removed.
  4. Ethernet PHY1(U19) RX ERROR Status signal "PRG1_CPSW_ETH1_LED_1000/RX_ER" is connected to
   SoC GPIO signal "PRG1_PRU0_GPO5". And the net  "GPIO_50" is removed from Boosterpack header J5
  Pin11.
  5. Ethernet PHY2 (U7) RX ERROR Status signal "PRG1_CPSW_ETH2_LED_1000/RX_ER" is connected to
  SoC GPIO signal "PRG1_PRU1_GPO5". And the signal "PRG_CPSW_RGMII1_MUX_SEL" is moved to
  GPMC0_AD12. USER_LED2 circuit (R7, R14, Q1 & LD4) is removed.
  6. PRG1_CPSW_ETH1_LED_ACT and PRG1_CPSW_ETH2_LED_ACT is connected to SoC GPIOs
  PRG1_PRU0_GPO9 & PRG1_PRU1_GPO9 respectively using R-Mux.
- 0.2
- 10th AUG 2021
- Mistral Design Team
- 0.3
- 11th AUG 2021
- Updated for Internal Review comments
- Mistral Design Team
- 1. The net "GPIO_RGMII1_PHY_RSTn" is moved from GPMC0_AD11 to  GPMC0_AD13.
  2. The net "FSI/BP_MUX_SEL" is moved from GPMC0_AD13 to  GPMC0_AD11.And the resistor R190 is
  DNI'd.
- 0.4
- 19th AUG 2021
- Mistral Design Team
- 1. Isolation Buffer for Bootmode Input pins 'U32'  Mfr. Part No. changed from SN74AVC8T245PWR
   to TXB0106PWR.
  2. Removed the IC U29 (SN74LVC1G04DCK) and capacitor C87.
  3.BOOTMODE0's Pull up Resistor R39 value changed from 10K to 49.9K
  BOOTMODE2's, BOOTMODE10's Pull down Resistor R206, R205  respectively  value changed from
  10K to 49.9K.
- 0.5
- 08th NOV 2021
- Mistral Design Team
- 0.6
- 15th NOV 2021
- 1. The Resistor R160 value changed from '1M' to '0E' and the capacitor C266 is DNI'd
- Mistral Design Team
sheet 2
- AM243x LAUNCH PAD
- TABLE OF CONTENTS
- PAGE
- CONTENTS
- 01
- TABLE OF CONTENTS
- 02
- REVISION HISTORY
- 03
- BLOCK DIAGRAM
- REV
- E3
- 04
- POWER TREE
- VER
- 1.0
- 05
- POWER ON SEQUENCE
- 06
- RESET ARCHITECTURE
- 07
- GPIO MAPPING TABLE
- 08
- I2C TREE
- 09
- BOOSTERPACK CONNECTOR PINOUTS
- 10
- RESET INPUTs
- 11
- SOC1
- 12
- SOC2
- 13
- MCAN_eQEP_FSI_MUX
- 14
- CAN_eQEP_FSI_HEADERs & CLOCK BUFFER
- 15
- QSPI_BOARD_ID_EEPROM
- 16
- ETHERNET DATA MUX & ADC INPUTS
- 17
- PRG/CPSW RGMII1 ETHERNET PHY
- 18
- PRG/CPSW RGMII2 ETHERNET PHY
- 19
- BOOSTERPACK CONNECTOR
- 20
- TEST AUTOMATION HEADER
- 21
- BOOT MODE BUFFER & SWITCHES
- 22
- XDS110 DEBUGGER
- 23
- INDUSTRIAL COMMUNICATION  LED's
- 24
- SoC Digital POWER & DECAPs
- 25
- SoC Analog POWER & DECAPs
- 26
- BOARD POWER INPUT & USB2.0
- 27
- BOARD POWER_01
- 28
- BOARD POWER_02
- 29
- HARDWARE SCHEMATICS
sheet 3
- BLOCK DIAGRAM
sheet 4
- POWER TREE
sheet 5
- POWER ON SEQUENCE
sheet 6
- RESET ARCHITECTURE
sheet 7
- GPIO MAPPING TABLE
sheet 8
- I2C TREE
sheet 9
- BOOSTERPACK CONNECTOR PINOUTs
sheet 10
- Reset Inputs
- MCU PORz Input
- Voltage monitor asserts the corresponding
  reset Signals low if :
- VDD_1V8 < 1.692V
  VSYS_3V3 < 3.12V
  VDD_CORE_0V85 < 0.794477V & VDD_CORE_0V85 > 0.90823V
- Delay for PORz is set 10.41 ms
- Reset Inputs from Boosterpacks
- PORz Input Push Button
- (From test Automation Header)
- SoC Warm Reset Input
- MCU Warm Reset Input
- User Push Button
- MCU Warm Reset Input Push Button
- SoC Warm Reset Input Push Button
- User Interrupt Input Push Button
- (From test Automation Header)
- (From test Automation Header)
- DEBOUNCE CIRCUIT
sheet 11
- SoC Blocks
- LPF For I2C Pins
- GPIO1_54
- GPIO1_55
- OBSCLK is used to source the RGMII2 Ethernet PHY
- Mount R240 & R185 and DNI R244 & R13 to source the RGMII2
  Ethernet PHY from OBSCLK
- LPF Designed for 25MHz Cutoff
  Have to change resistor and capacitor values accordingly
- UART Buffer & EXT UART HDR for UART1
- SoC_Connections
- Header_Connections
- MAIN_UART1_TXD
- UART1_HDR_RXD - Pin5
- GPIO1_25
- MAIN_UART1_RXD
- UART1_HDR_TXD - Pin4
- MAIN_UART1_RTS#
- UART1_HDR_CTS# - Pin2
- GPIO1_28
- MAIN_UART1_CTS#
- UART1_HDR_RTS# - Pin6
- Isolation Buffer for Bootmode Input pins
- BOOT Mode Pins
- GPIO1_38
- GPIO1_39
- GPIO0_22
- GPIO0_26
- GPIO0_27
- GPIO0_28
- (To FSI Header)
- Note : No Input to SoC should be driven
  from others while Booting
- Note: 1K resistors are used to isolate the
  BOOTMODE control logic after the value is latched
